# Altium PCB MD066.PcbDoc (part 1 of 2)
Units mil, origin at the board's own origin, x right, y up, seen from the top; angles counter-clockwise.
Board outline 4255 x 2850 mil, 4 copper layers (Top Layer, Ground, Power, Bottom Layer), stack 61.6 mil thick; 158 components, 78 nets, 405 pads, 639 vias.
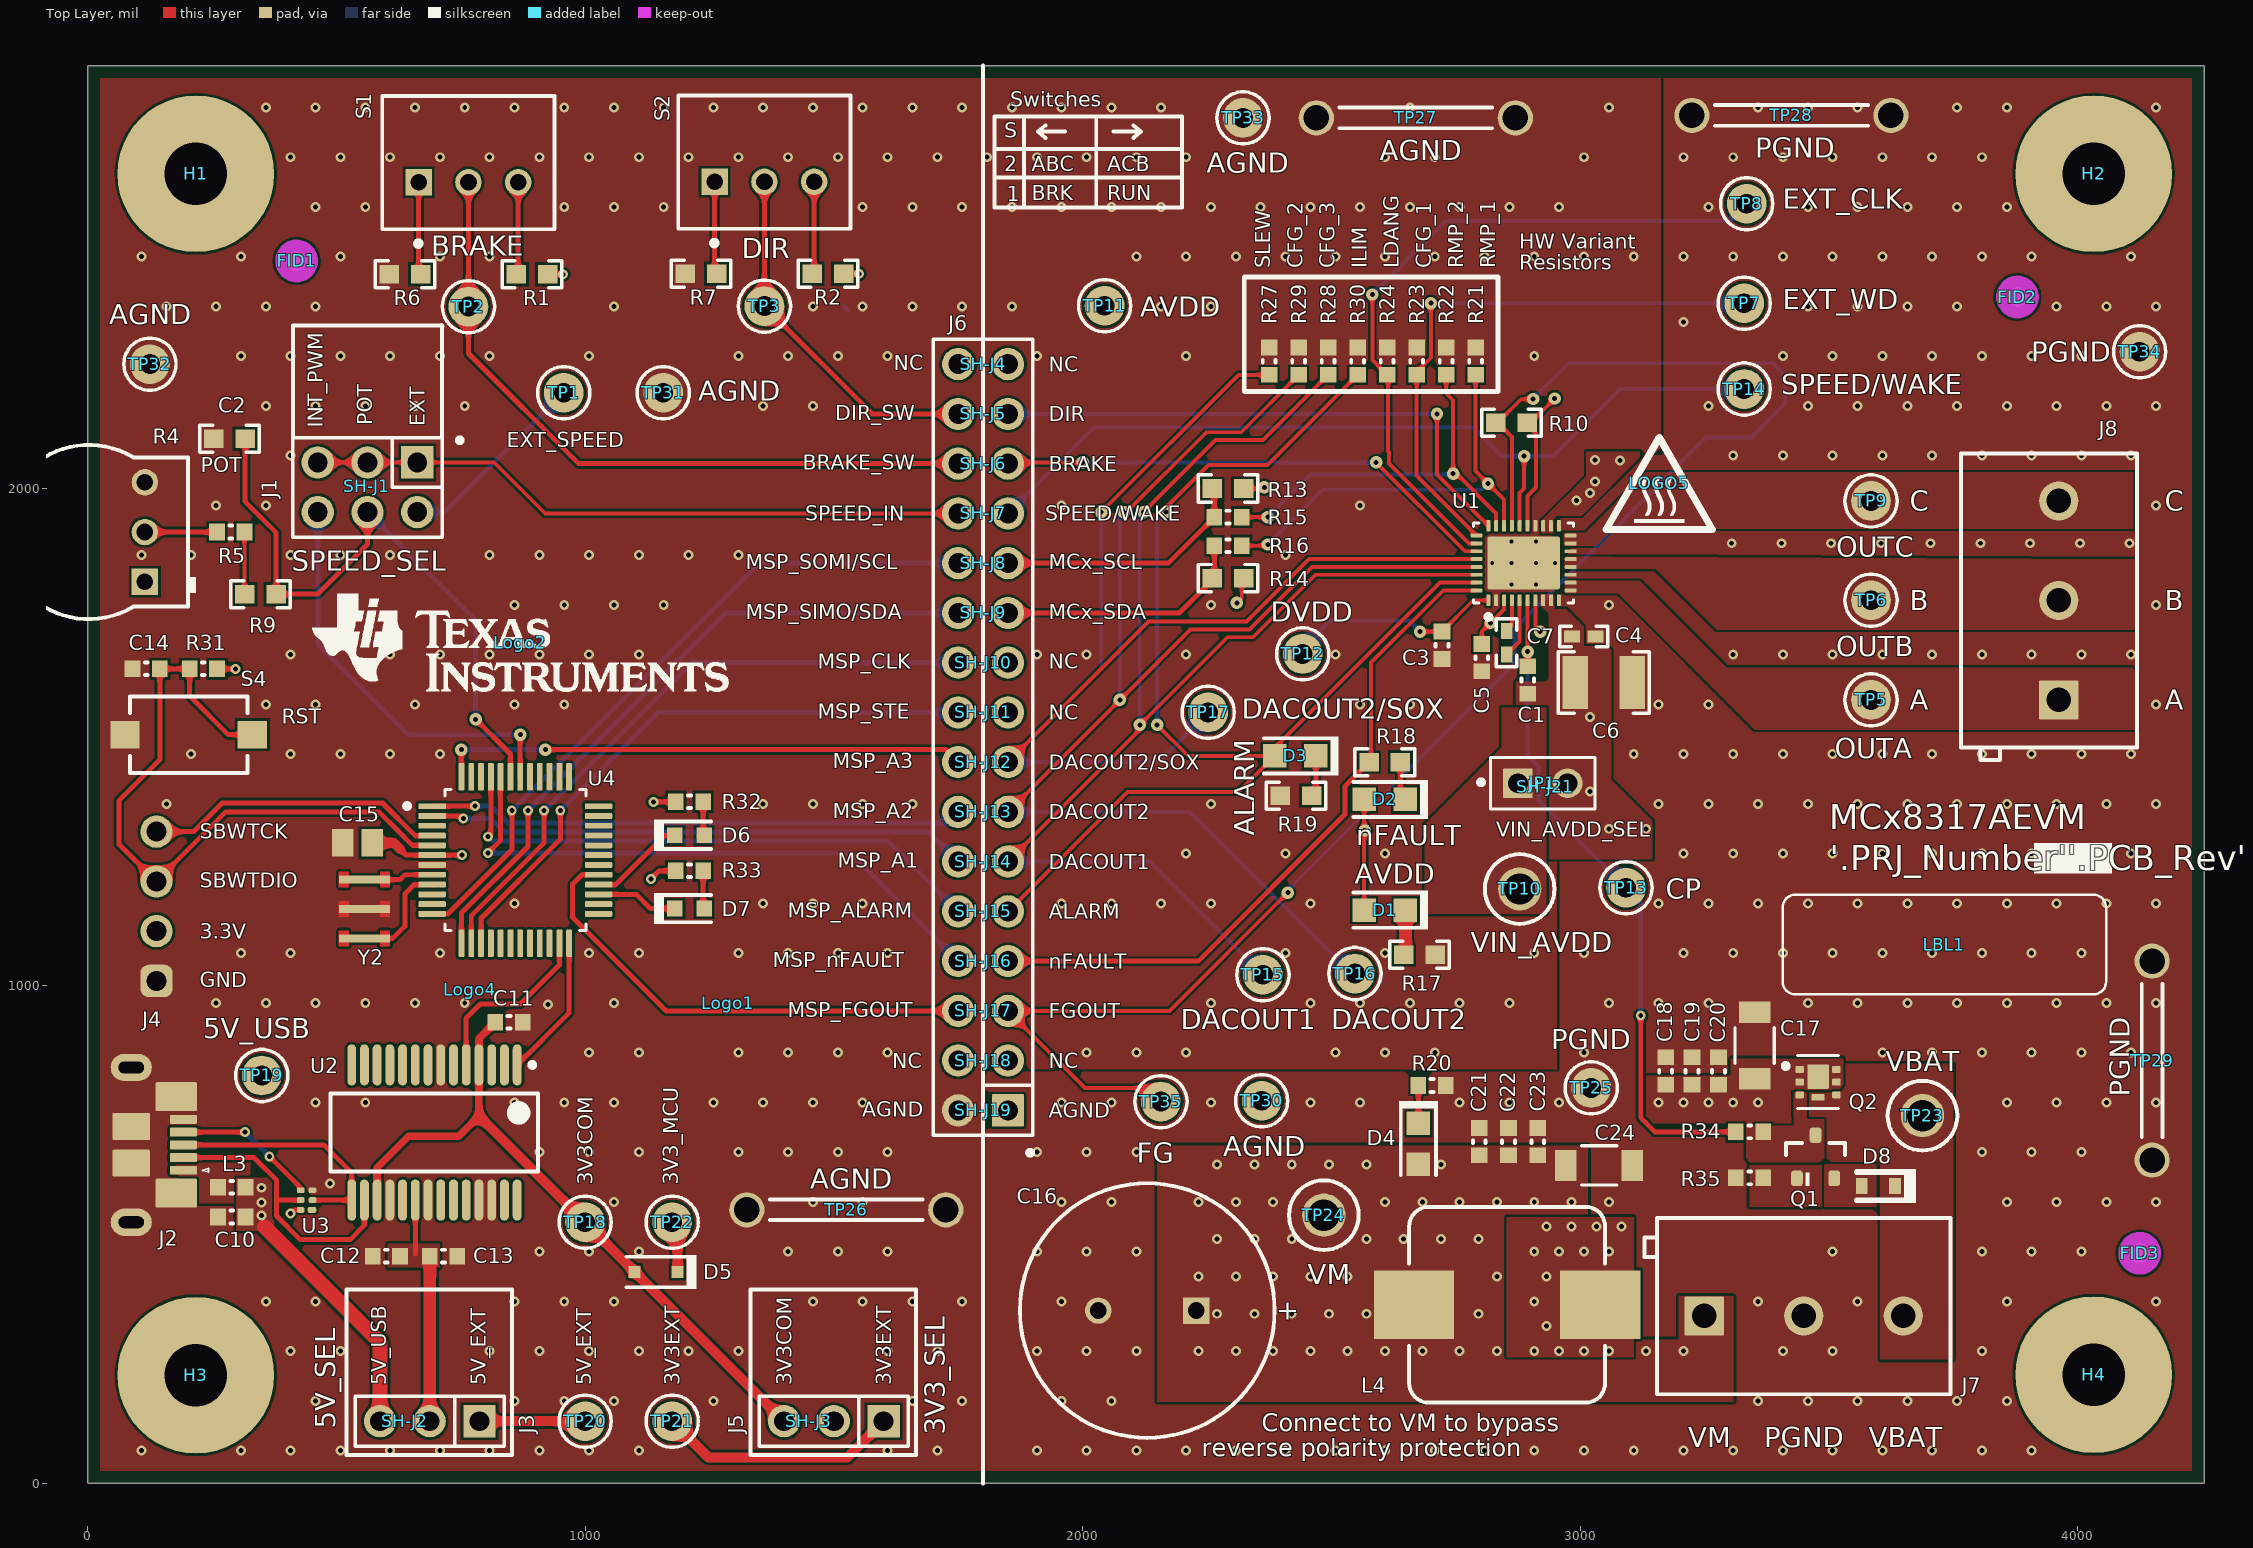
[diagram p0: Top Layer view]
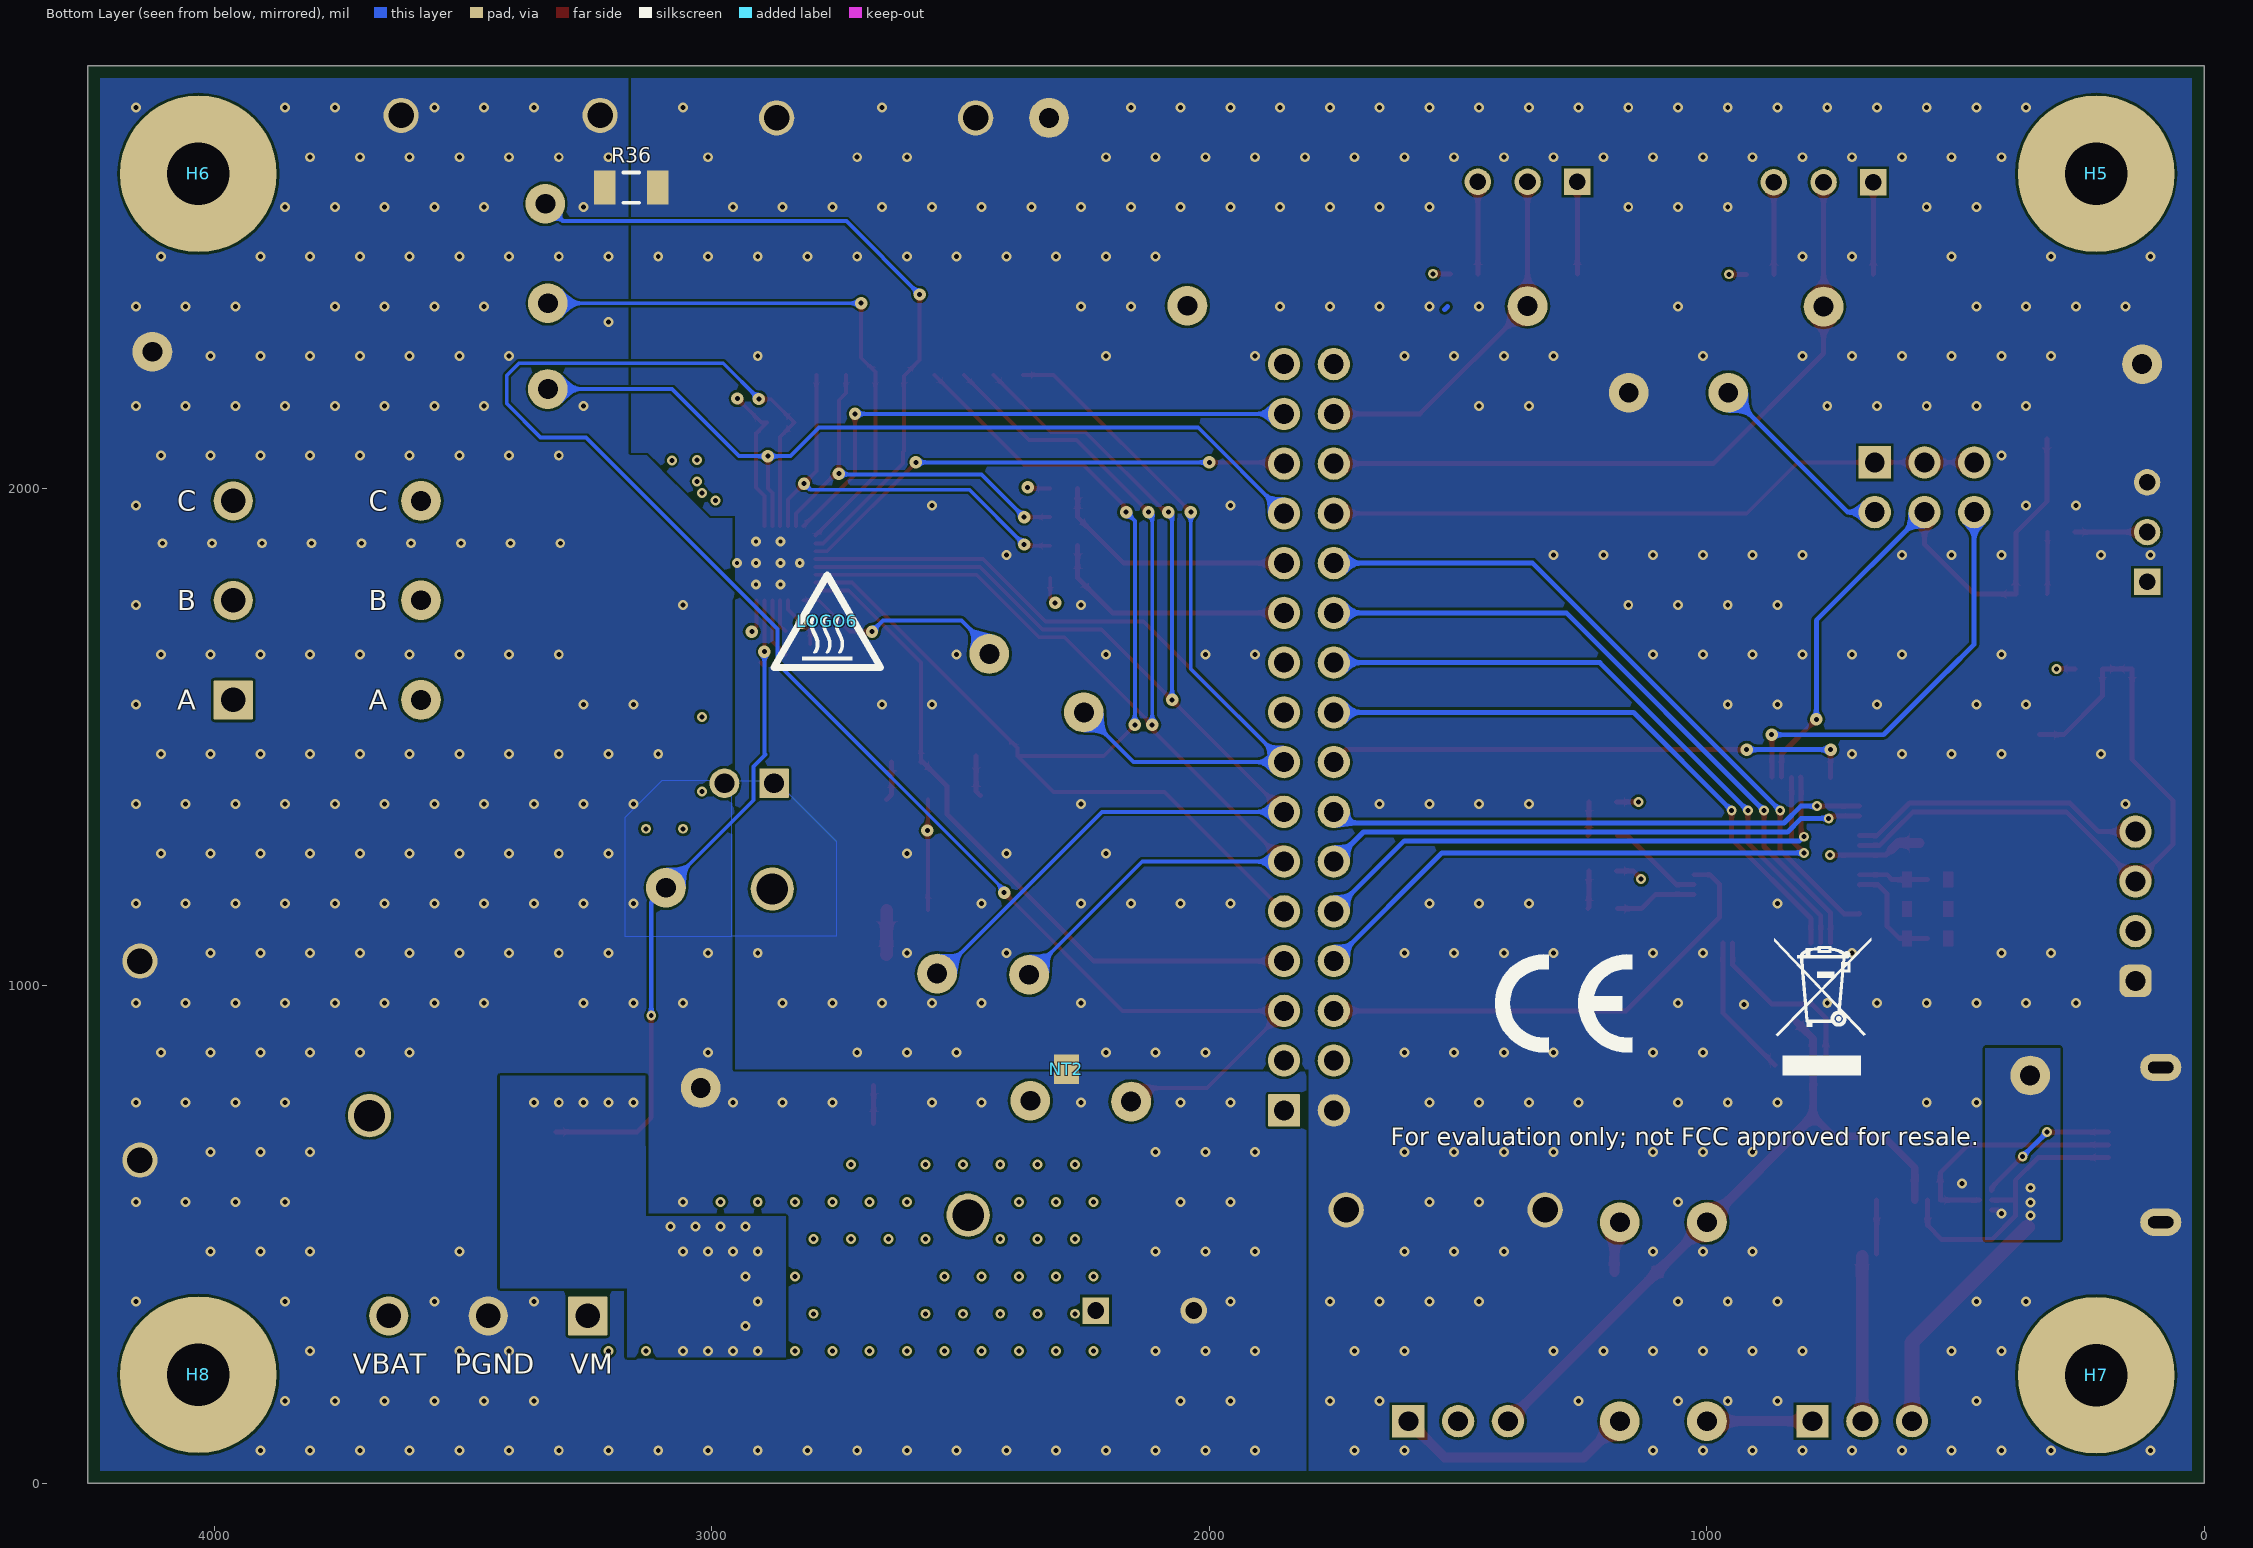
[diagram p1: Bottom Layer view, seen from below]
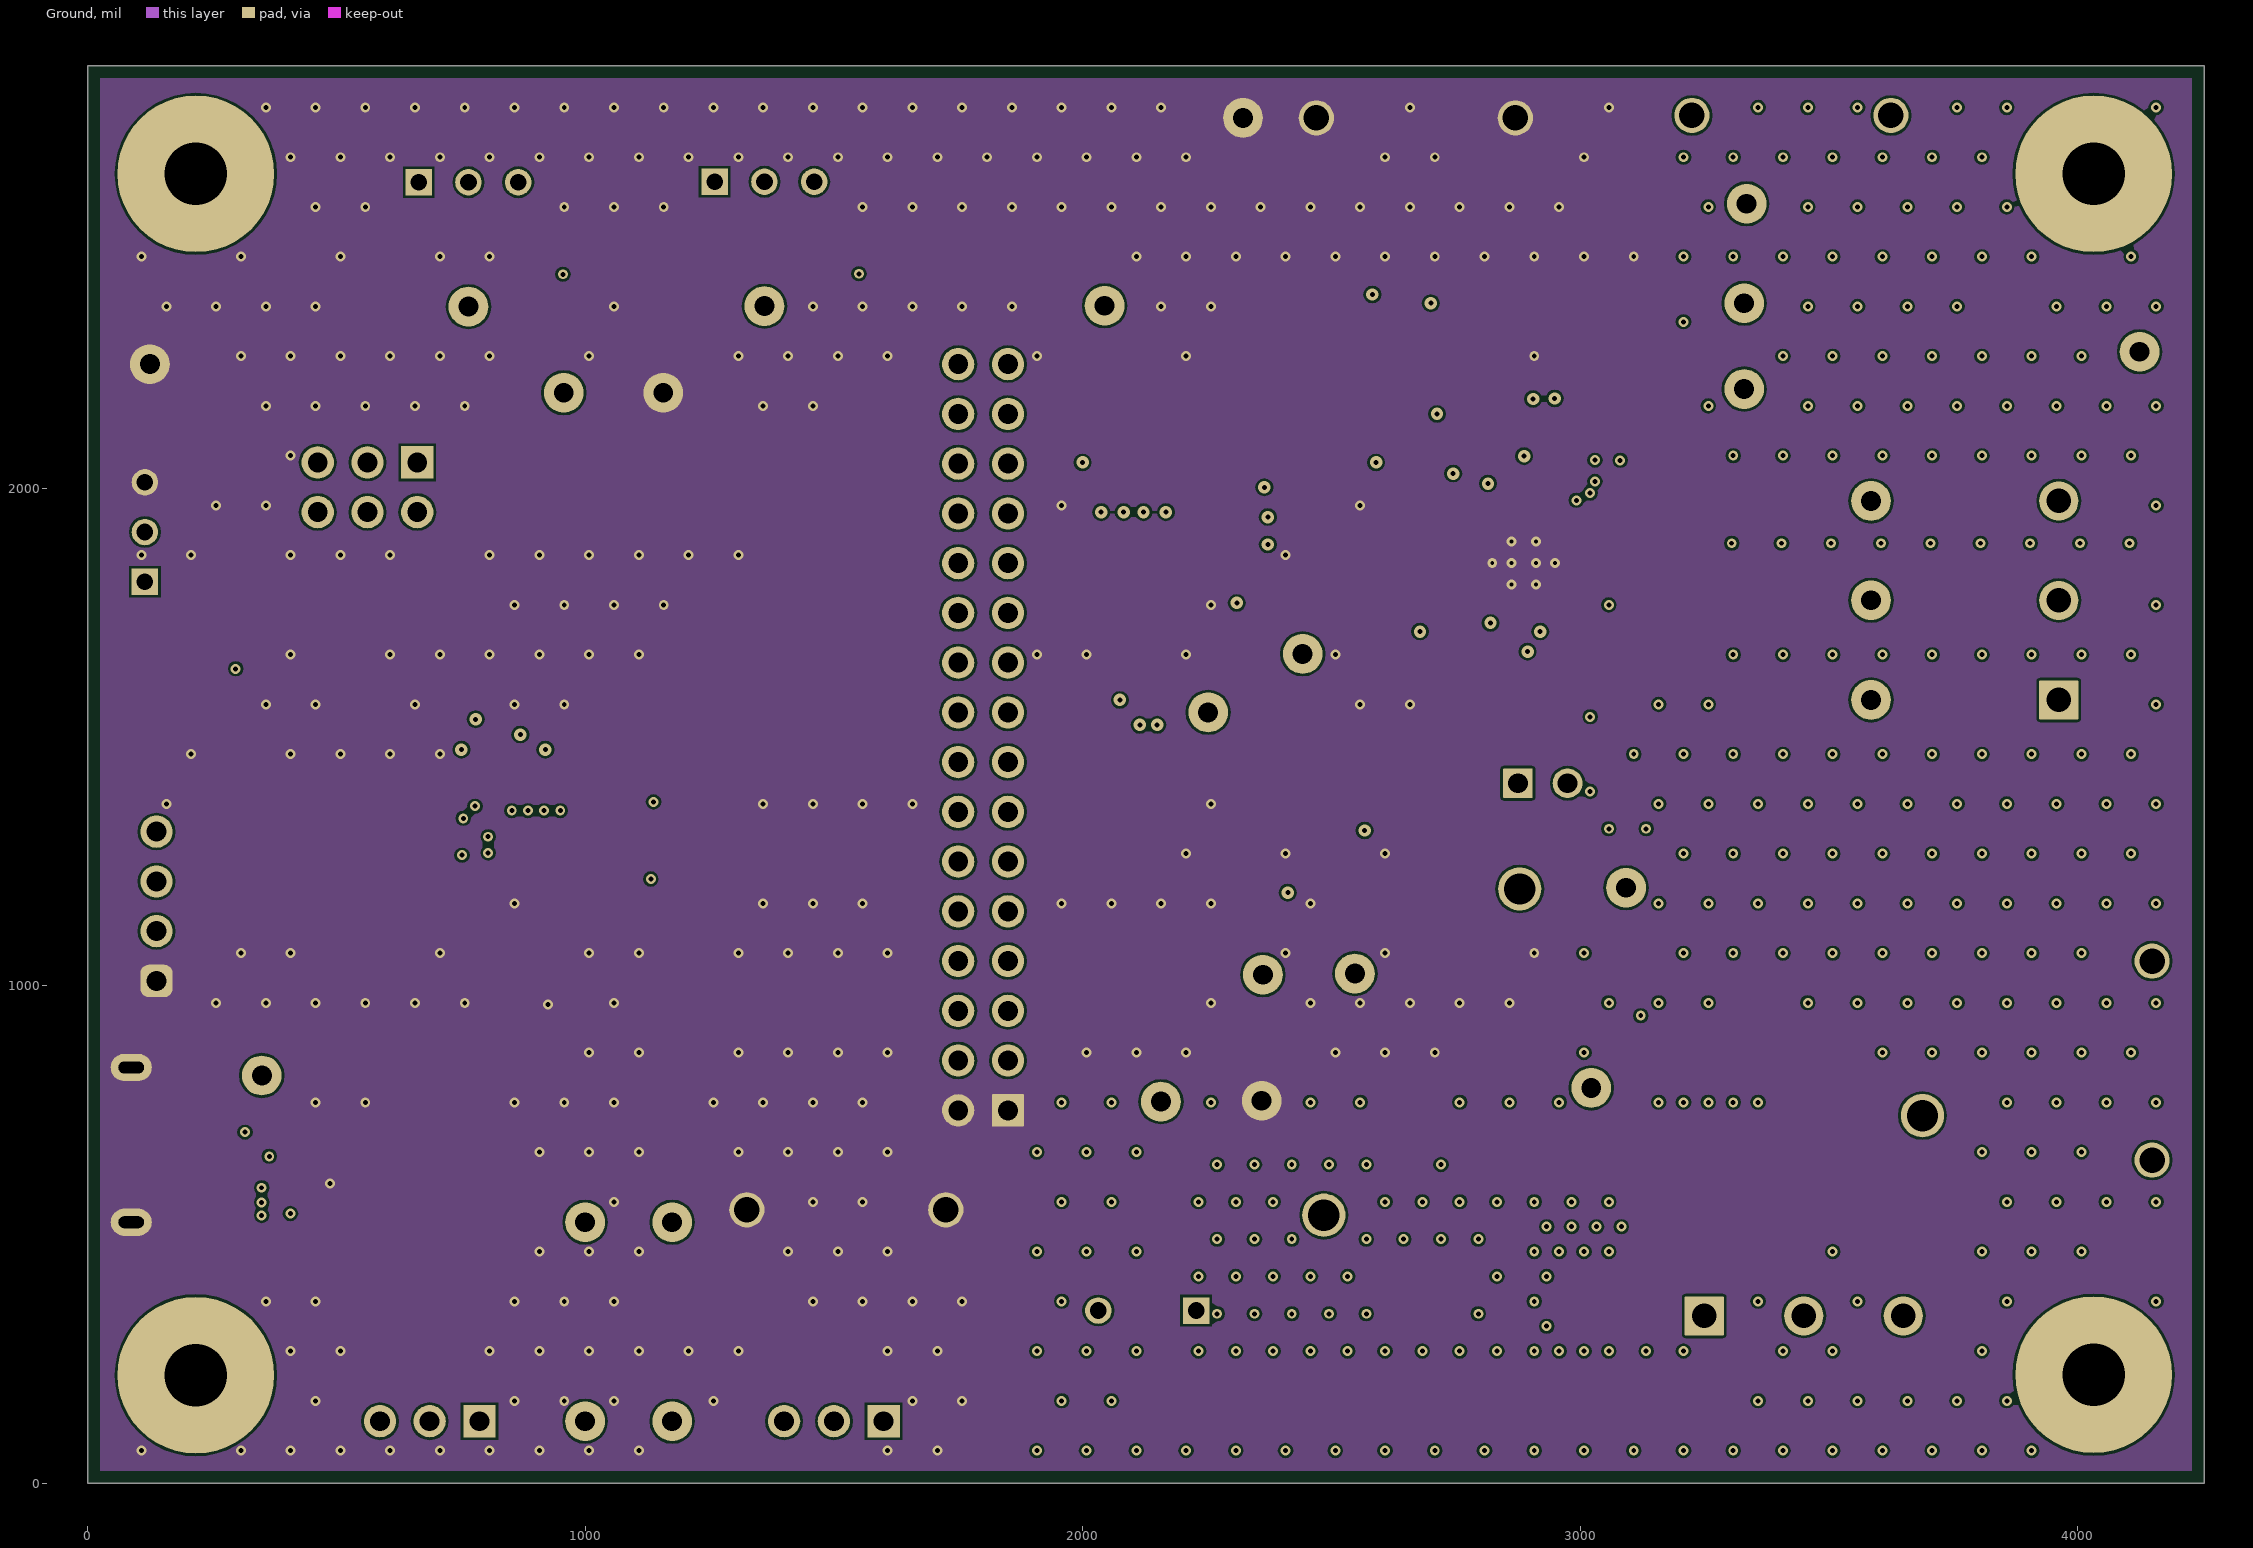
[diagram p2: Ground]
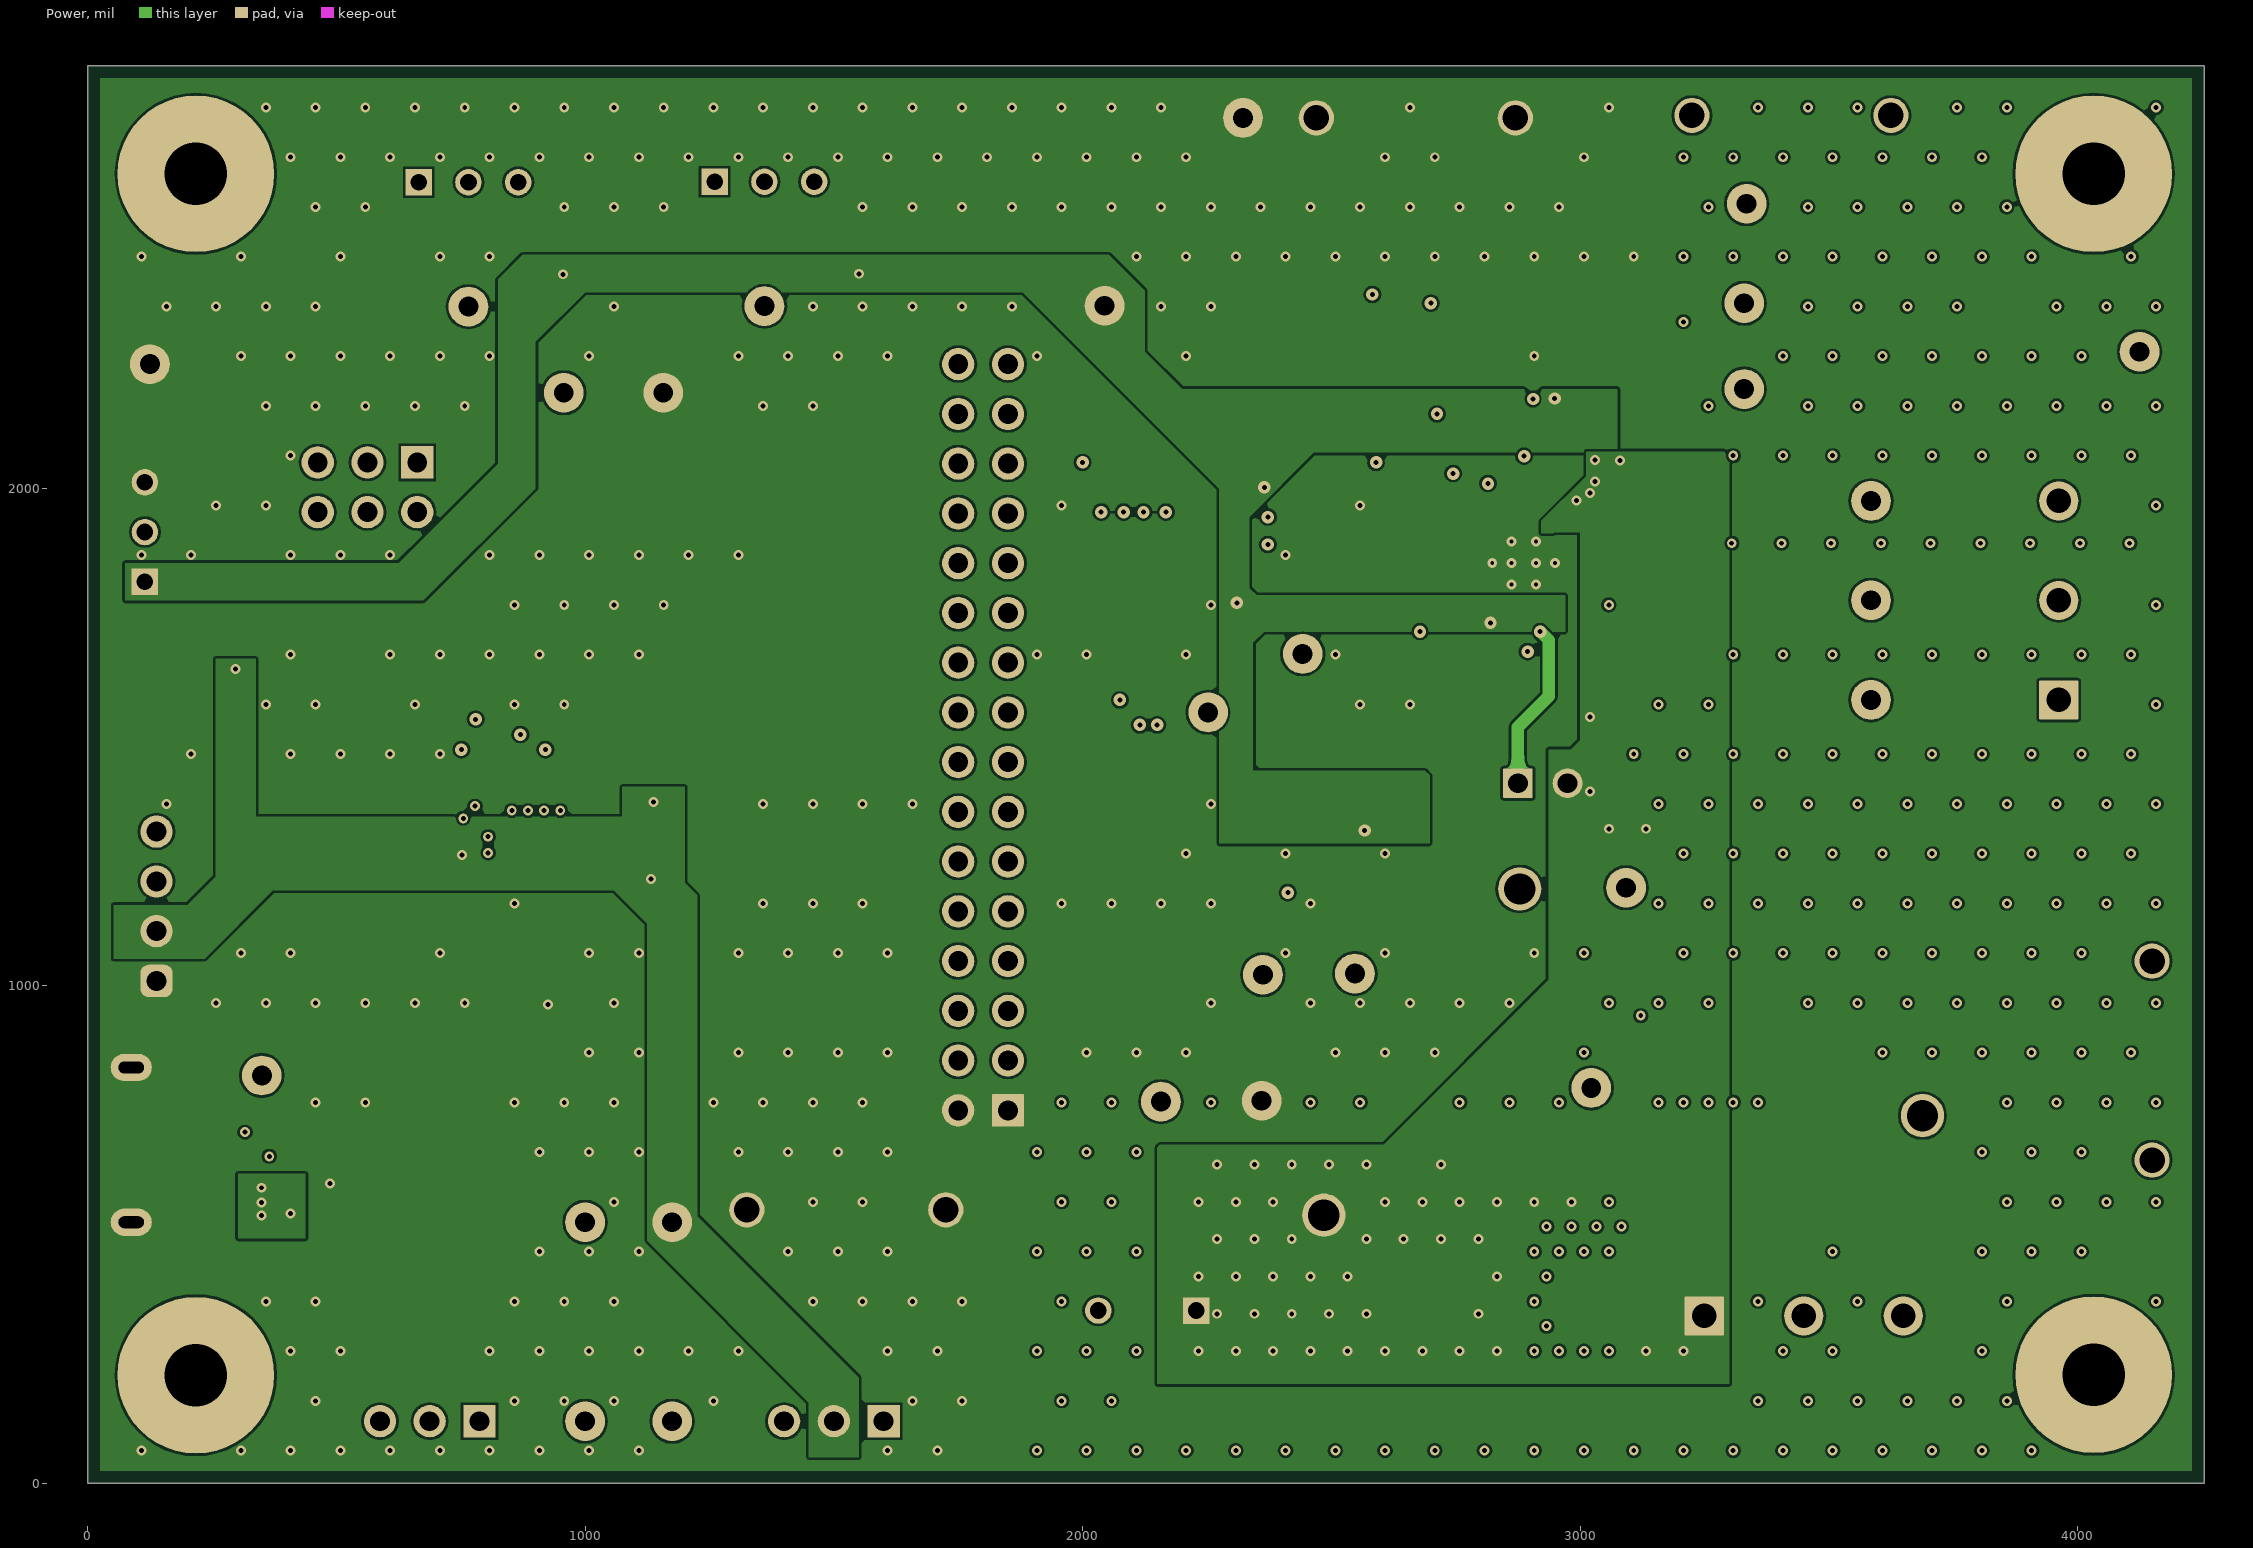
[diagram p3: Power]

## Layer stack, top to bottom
Top Solder: solder mask 0.4, Solder Resist, Dk 3.5
Top Layer: signal copper 1.4
Dielectric 1: prepreg 8, FR-4, Dk 4.2
Ground: signal copper 1.4
Dielectric 2: core 40, FR-4, Dk 4.2
Power: signal copper 1.4
Dielectric 3: prepreg 8, FR-4, Dk 4.2
Bottom Layer: signal copper 1.4
Bottom Solder: solder mask 0.4, Solder Resist, Dk 3.5

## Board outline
0,0 0,2850 4255,2850 4255,0

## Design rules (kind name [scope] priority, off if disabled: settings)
AcuteAngle [All] p1: minimum=4.50000000000000E+0001 checktracksonly=FALSE
AssemblyTestPointUsage [All] p1: valid=2
BoardOutlineClearance BoardOutlineClearance_MountingHoles [OnCopper and InComponentClass('Mounting Holes')] p1: gap=39.37 ignorepadtopadclearanceinfootprint=FALSE
BoardOutlineClearance BoardOutlineClearance_Poly [OnCopper and IsPoly] p2: gap=25 ignorepadtopadclearanceinfootprint=FALSE
BoardOutlineClearance [OnCopper and Not InComponentClass('Logo') and not InComponentClass('FiducialMark') and not InRegion(1000,500,4000,800) and not InPoly] p3: gap=30 ignorepadtopadclearanceinfootprint=FALSE
Clearance "Stitching AGND" [IsStitchingVia and InNet('AGND') vs (IsVia and (Not IsStitchingVia)) Or IsPad] p1: gap=70 ignorepadtopadclearanceinfootprint=TRUE
Clearance Clearance_Keepouts [((IsTrack Or IsArc) And Not InPoly) And IsFree and IsKeepOut vs ((IsTrack Or IsArc) And Not InPoly) And IsFree and IsKeepOut] p2: gap=0 ignorepadtopadclearanceinfootprint=FALSE
Clearance Clearance_Poly [InPolygon] p3: gap=7.87 ignorepadtopadclearanceinfootprint=TRUE except(5: Arc-Fill Arc-Poly Arc-Region Track-Fill Track-Poly Track-Region SMDPad-Fill SMDPad-Poly SMDPad-Region THPad-Fill THPad-Poly THPad-Region Via-Fill Via-Poly Via-Region Fill-Fill Fill-Poly Fill-Region Poly-Poly Poly-Region Region-Region)
Clearance Clearance_FiducialMark [IsKeepOut and InComponentClass('FiducialMark') vs IsPad and InComponentClass('FiducialMark')] p4: gap=0 ignorepadtopadclearanceinfootprint=FALSE
Clearance [All] p5: gap=7.87 ignorepadtopadclearanceinfootprint=TRUE
ComponentClearance ComponentClearance_MountingHoles_FiducialMarks [InComponentClass('Mounting Holes') vs InComponentClass('FiducialMark')] p1: gap=50 collisioncheckmode=3 verticalgap=10 showdistances=FALSE
ComponentClearance ComponentClearance_Shunt [InComponentClass('Header') vs InComponentClass('Shunt')] p2: gap=0 collisioncheckmode=3 verticalgap=0 showdistances=FALSE
ComponentClearance ComponentClearance_Logo [InComponentClass('Logo')] p3: gap=50 collisioncheckmode=3 verticalgap=10 showdistances=FALSE
ComponentClearance ComponentClearance_ScrewToNut [(HasFootprint('NY PMS 440 0025 PH')) vs (HasFootprint('Keystone_1902C'))] p4: gap=5 collisioncheckmode=3 verticalgap=10 showdistances=FALSE
ComponentClearance ComponentClearance_MountingHoles [InComponentClass('Mounting Holes')] p5: gap=150 collisioncheckmode=3 verticalgap=100000 showdistances=FALSE
ComponentClearance ComponentClearance_SmallPassives [HasFootprint('0201*') or HasFootprint('0402*') or HasFootprint('0508') or HasFootprint('0603*') or HasFootprint('0612') or HasFootprint('0805*') or HasFootprint('0815*') or HasFootprint('0830*') or HasFootprint('1206*') or HasFootprint('1210*') or HasFootprint('1808*') or HasFootprint('1812*') or HasFootprint('1825*') or HasFootprint('2010*') or HasFootprint('2220*') or HasFootprint('2225*') or HasFootprint('2512*') or HasFootprint('2728*') or HasFootprint('3518*') vs HasFootprint('0201*') or HasFootprint('0402*') or HasFootprint('0508') or HasFootprint('0603*') or HasFootprint('0612') or HasFootprint('0805*') or HasFootprint('0815*') or HasFootprint('0830*') or HasFootprint('1206*') or HasFootprint('1210*') or HasFootprint('1808*') or HasFootprint('1812*') or HasFootprint('1825*') or HasFootprint('2010*') or HasFootprint('2220*') or HasFootprint('2225*') or HasFootprint('2512*') or HasFootprint('2728*') or HasFootprint('3518*')] p6: gap=14.96 collisioncheckmode=3 verticalgap=10 showdistances=FALSE
ComponentClearance ComponentClearance_THtoSMT [IsThruComponent vs IsSMTComponent] p7: gap=0 collisioncheckmode=3 verticalgap=0 showdistances=FALSE
ComponentClearance ComponentClearance_THtoTH [IsThruComponent vs IsThruComponent] p8: gap=0 collisioncheckmode=3 verticalgap=0 showdistances=FALSE
ComponentClearance [All] p9: gap=0 collisioncheckmode=3 verticalgap=0 showdistances=FALSE
DiffPairsRouting [All] p1: maxlimit=100 minlimit=10 mostfreqgap=10 toplayer_minwidth=15 toplayer_maxwidth=15 toplayer_prefwidth=15 midlayer1_minwidth=15 midlayer1_maxwidth=15 midlayer1_prefwidth=15 midlayer2_minwidth=15 midlayer2_maxwidth=15 midlayer2_prefwidth=15 bottomlayer_minwidth=15 bottomlayer_maxwidth=15 bottomlayer_prefwidth=15 maxuncoupledlength=1000
FabricationTestPointUsage TestPointUsage [All] p1: valid=2 allowmultiple=FALSE
FabricationTestpoint Testpoint [All] p1: side=3 testpointundercomponent=TRUE minsize=40 maxsize=100 preferedsize=60 minholesize=0 maxholesize=40 preferedholesize=32 testpointgrid=1 allowsidetop=TRUE allowsidebottom=TRUE usegrid=TRUE gridtolerance=0.01
FanoutControl Fanout_LCC [IsLCC] p1: bgadir=Out bgaviamode=Centered fanoutstyle=Auto fanoutdirection=Alternating viagrid=1 // Fanout_LCC (Default Rule)
FanoutControl Fanout_BGA [IsBGA] p2: bgadir=Out bgaviamode=Centered fanoutstyle=Auto fanoutdirection=Alternating viagrid=1 // Fanout_BGA (Default Rule)
FanoutControl Fanout_Default [All] p4: bgadir=Out bgaviamode=Centered fanoutstyle=Auto fanoutdirection=Alternating viagrid=1 // Fanout_Default (Default Rule)
FanoutControl Fanout_Small [(CompPinCount < 5)] p5: bgadir=Out bgaviamode=Centered fanoutstyle=Auto fanoutdirection=OutThenIn viagrid=1 // Fanout_Small (Default Rule)
HoleSize [All] p1: absolutevalues=TRUE maxlimit=200 minlimit=1 maxpercent=80.000 minpercent=20.000
MinimumAnnularRing MinimumAnnularRing_ThermalPadVias [IsVia and InAnyComponent] p1: minimumring=1
MinimumAnnularRing [All] p2: minimumring=1
MinimumSolderMaskSliver MinimumSolderMaskSliver_Logo [InComponentClass('Logo') vs InComponentClass('Logo')] p1: minsoldermaskwidth=0.7
MinimumSolderMaskSliver [All] p2: minsoldermaskwidth=1
PlaneConnect [All] p1: planeconnectstyle=Relief reliefexpansion=10 reliefentries=4 reliefconductorwidth=10 reliefairgap=10
PolygonConnect [All] p1: connectstyle=Direct reliefconductorwidth=10 reliefentries=4 polygonreliefangle="90 Angle" airgapwidth=10
RoutingVias ThermalPadVias [IsVia and InAnyComponent] p1: holewidth=7.87 width=19.68 viastyle="Through Hole" minholewidth=7.87 minwidth=19.68 maxholewidth=12.99 maxwidth=23.62
RoutingVias [All] p2: holewidth=10 width=25 viastyle="Through Hole" minholewidth=7 minwidth=20 maxholewidth=15 maxwidth=30
SilkToBoardRegionClearance [Not ((IsComment or IsDesignator) And (Hide <> 'False')) and not InRegion(1000,500,4000,800)] p1:
SilkToSilkClearance SilkToSilkClearance_Pb-FreeLogo [(HasFootprint('Pb-Free_Overlay_Medium') OR HasFootprint('Pb-Free_Overlay_Small')) vs (HasFootprint('Pb-Free_Overlay_Medium') OR HasFootprint('Pb-Free_Overlay_Small'))] p1: silktosilkclearance=1
SilkToSilkClearance [All] p2: silktosilkclearance=1
SilkToSolderMaskClearance [IsPad] p1: minsilkscreentomaskgap=1 clearancetoexposedcopper=TRUE
SolderMaskExpansion [All] p1: expansion=1.97
UnRoutedNet [All] p1: checkbadconnections=TRUE
Width [All] p1: maxlimit=100 minlimit=6 preferedwidth=10 checkconnectedcopper=TRUE
14 further rules are at their usual default settings.

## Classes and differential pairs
component class Label: LBL1
component class "Mounting Holes": H1 H2 H3 H4
component class MD066_INTERFACE: C10 C11 C12 C13 C14 C15 D5 D6 D7 J2 J3 J4 J5 J6 L3 R31 R32 R33 S4 SH-J2 SH-J3 SH-J4 SH-J5 SH-J6 SH-J7 SH-J8 SH-J9 SH-J10 SH-J11 SH-J12 SH-J13 SH-J14 SH-J15 SH-J16 SH-J17 SH-J18 SH-J19 TP18 TP19 TP20 TP21 TP22 U2 U3 U4 Y2
component class MD066_CONTROL: C2 J1 R1 R2 R4 R5 R6 R7 R9 S1 S2 SH-J1 TP1 TP2 TP3
component class Shunt: SH-J1 SH-J2 SH-J3 SH-J4 SH-J5 SH-J6 SH-J7 SH-J8 SH-J9 SH-J10 SH-J11 SH-J12 SH-J13 SH-J14 SH-J15 SH-J16 SH-J17 SH-J18 SH-J19 SH-J21
component class MD066_POWER_AND_CONNECTORS: AGND AGND1 C16 C17 C18 C19 C20 C21 C22 C23 C24 D8 J7 J8 J10 J11 JP1 L4 NT2 PGND PGND2 PGND3 Q1 Q2 R34 R35 R36 R45 SH-J21 TP10 TP23 TP24 TP25 TP26 TP27 TP28 TP29 TP30 TP31 TP32 TP33 TP34 TP_AGND1 TP_AGND2 TP_PGND vm VM1
component class MD066_DRIVER: 1 A1 B1 C1 C3 C4 C5 C6 C7 D1 D2 D3 D4 D? ILIM1 R10 R13 R14 R15 R16 R17 R18 R19 R20 R21 R22 R23 R24 R27 R28 R29 R30 TP5 TP6 TP7 TP8 TP9 TP11 TP12 TP13 TP14 TP15 TP16 TP17 TP35 U1
component class Header: J1 J3 J4 J5 J6 J10
component class Logo: Logo2
component class MD066_HARDWARE: FID1 FID2 FID3 H1 H2 H3 H4 H5 H6 H7 H8 LBL1 Logo1 Logo2 Logo3 Logo4 LOGO5 LOGO6 ZZ1 ZZ2 ZZ3 ZZ4
component class FiducialMark: FID1 FID2 FID3
component class AssemblyNote: ZZ1 ZZ2 ZZ3 ZZ4

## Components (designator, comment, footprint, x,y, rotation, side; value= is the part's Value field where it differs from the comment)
C1 "EMK107B7105KAHT" 0603L 2894.94,1615 r270 top value=1uF
C2 "0603ZC101KAT2A" 0603 285,2100 r180 top value=100pF
C3 "C0603C105K9RACAUTO" 0603L 2722.5,1685 r90 top value=1uF
C4 "C1005X6S1H104K050BB" 0402 3007.5,1702.5 r0 top value=0.1uF
C5 "C0603C105K9RACAUTO" 0603L 2802.5,1660 r90 top value=1uF
C6 "GRM32ER71J106KA12L" 1210_270 3047.5,1610 r0 top value=10uF
C7 "C1005X6S1H104K050BB" 0402 2852.5,1690 r90 top value=0.1uF
C10 "0603ZC104KAT2A" 0603L 289.64,535.59 r180 top value=0.1uF
C11 "0603ZC104KAT2A" 0603L 847.14,927.09 r0 top value=0.1uF
C12 "GRM188Z71A475ME15D" 0603L 600.29,456.84 r0 top value=4.7uF
C13 "0603ZC104KAT2A" 0603L 715.29,456.96 r0 top value=0.1uF
C14 "885012206034" 0603L 117.5,1637.5 r180 top value=1000pF
C15 "885012207103" 0805L 542.5,1287.5 r180 top value=1uF
C16 "ELXZ630ELL331MK20S" Chemi-Con_1250x2000 2130,347.5 r180 top value=330uF
C17 "CL31B105KCHNNNE" 1206_180 3350.96,880.34 r90 top value=1uF
C18 "CGA3E3X7S2A104K080AB" 0603L 3172.01,828.83 r90 top value=0.1uF
C19 "CGA3E2X7R2A103K080AA" 0603L 3225.22,828.83 r90 top value=0.01uF
C20 "CGA3E2X7R2A102K080AA" 0603L 3278.42,828.83 r90 top value=1000pF
C21 "CGA3E2X7R2A102K080AA" 0603L 2797.51,686.94 r90 top value=1000pF
C22 "CGA3E2X7R2A103K080AA" 0603L 2856.26,686.94 r90 top value=0.01uF
C23 "CGA3E3X7S2A104K080AB" 0603L 2915.01,686.94 r90 top value=0.1uF
C24 "CL31B105KCHNNNE" 1206_180 3038.46,639.14 r0 top value=1uF
D1 "AVDD" LTST-C170KGKT_Green 2607.5,1152.5 r0 top value=Green
D2 "nFAULT" LED_LTST-C170_Red 2607.5,1375 r0 top value=Red
D3 "ALARM" LED_LTST-C170_Red 2427.5,1462.5 r0 top value=Red
D4 "LTST-C170KGKT" LTST-C170KGKT_Green 2675,682.5 r90 top value=Green
D5 "BAT165E6327HTSA1" SOD-323 1142.5,425 r180 top value=40V
D6 "LTST-C190KRKT" LED_LTST-C190_Red 1209.64,1302.7 r180 top value=Red
D7 "LTST-C190GKT" LED_LTST-C190 1209.64,1155.59 r180 top value=Green
D8 "CDSU101A" SOD-523F 3599.64,597.8 r180 top value=90V
FID1 "Fiducial" Fiducial10-20 420,2457.5 r0 top
FID2 "Fiducial" Fiducial10-20 3879.4,2385 r0 top
FID3 "Fiducial" Fiducial10-20 4125,462.5 r0 top
H1 "NY PMS 440 0025 PH" "NY PMS 440 0025 PH" 217.5,2632.5 r0 top
H2 "NY PMS 440 0025 PH" "NY PMS 440 0025 PH" 4032.5,2632.5 r0 top
H3 "NY PMS 440 0025 PH" "NY PMS 440 0025 PH" 217.5,217.5 r0 top
H4 "NY PMS 440 0025 PH" "NY PMS 440 0025 PH" 4032.5,218.36 r0 top
H5 "Nut" Keystone_1902C 217.5,2632.5 r180 bottom
H6 "Nut" Keystone_1902C 4032.5,2632.5 r180 bottom
H7 "Nut" Keystone_1902C 217.5,217.5 r180 bottom
H8 "Nut" Keystone_1902C 4032.5,218.36 r180 bottom
J1 "SPEED_CTRL_SEL" TSW-103-07-G-D 562.5,2002.5 r180 top
J2 "1051640001" Molex_1051640001 30.41,680.59 r270 top
J3 "Header_3x1" PBC03SAAN 687.5,125 r180 top
J4 "TSW-104-07-G-S" TSW-104-07-G-S 138.36,1160.18 r90 top
J5 "Header_3x1" PBC03SAAN 1500,125 r180 top
J6 "TSW-116-07-G-D" TSW-116-07-G-D 1800,1500 r90 top
J7 "MOTOR_OUT" On-Shore_ED120_3DS 3449.83,336.64 r0 top
J8 "MOTOR_OUT" On-Shore_ED120_3DS 3962.5,1775 r90 top
JP1 "VIN_AVDD_SEL" FP-MTLW-102-07-G-S-230_HDR2-MFG 2925,1407.5 r0 top
L3 "BLM18SG121TZ1D" 0603L 289.64,595.24 r180 top
L4 "SRP1038A-1R0M" SRP1038A 2853.46,359.14 r180 top value=1uH
LBL1 "THT-14-423-10" Label_650x200 3732.5,1083.2 r180 top
Logo1 "CE Mark" CE_Mark_5mm 1287.85,965 r180 top
Logo2 "Texas Instruments" TI_Stacked_Overlay_Small 870,1690 r0 top
Logo3 "FCC disclaimer" FCC_disclaimer 8817.5,5262.5 r90 top
Logo4 "WEEE logo" WEEE_Minimum 769.14,992.5 r180 top
LOGO5 "CAUTION HOT SURFACE" IEC_HotSurface_Small 3159.37,2010.26 r0 top
LOGO6 "CAUTION HOT SURFACE" IEC_HotSurface_Small 2768.31,1733.62 r180 bottom
NT2 "Net-Tie" Net-Tie_50milWide_30milLong 2287.5,832.5 r270 bottom net-tie
Q1 "FMMT620TA" SOT-23L 3473.46,656.64 r90 top value="80 V"
Q2 "BUK9D23-40EX" FP-BUK9D23-40EX_SOT1220-MFG 3478.46,806.64 r0 top
R1 "RNCF0603TKY10K0" 0603 893,2430.7 r0 top value=10.0k
R2 "RNCF0603TKY10K0" 0603 1488,2431.7 r0 top value=10.0k
R4 "3352T-1-253LF" Bourns_3352T 115,1912.5 r90 top value="25 kohm"
R5 "ERJ-3GEY0R00V" 0603L 287.5,1912.5 r180 top value=0
R6 "RNCF0603TKY10K0" 0603 637.94,2430.7 r0 top value=10.0k
R7 "RNCF0603TKY10K0" 0603 1232.88,2431.7 r0 top value=10.0k
R9 "RT0603BRD0747RL" 0603 347.5,1787.5 r180 top value=47.0
R10 "RCG060310K0FKEA" 0603 2862.03,2132.5 r0 top value=10.0k
R13 "RT0603DRE071K74L" 0603 2292.5,2000 r0 top value=1.74k
R14 "RT0603DRE071K74L" 0603 2292.5,1820 r0 top value=1.74k
R15 "ERJ-3GEY0R00V" 0603L 2292.5,1942.5 r0 top value=0
R16 "ERJ-3GEY0R00V" 0603L 2292.5,1885 r0 top value=0
R17 "RC0603FR-071KL" 0603 2677.5,1062.5 r180 top value=1.00k
R18 "RC0603FR-071KL" 0603 2607.5,1450 r0 top value=1.00k
R19 "ERJ-3GEYJ222V" 0603 2428.98,1382.5 r0 top value=2.2k
R20 "RT0603BRD074K7L" 0603L 2702.56,800 r180 top value=4.70k
R21 "ERJ-3GEY0R00V" 0603L 2790.1,2256 r90 top value=0
R22 "ERJ-3GEY0R00V" 0603L 2730.8,2256 r90 top value=0
R23 "ERJ-3GEY0R00V" 0603L 2671.5,2256 r90 top value=0
R24 "ERJ-3GEY0R00V" 0603L 2612.2,2256 r90 top value=0
R27 "ERJ-3GEY0R00V" 0603L 2375,2256 r90 top value=0
R28 "ERJ-3GEY0R00V" 0603L 2493.6,2256 r90 top value=0
R29 "ERJ-3GEY0R00V" 0603L 2434.3,2256 r90 top value=0
R30 "ERJ-3GEY0R00V" 0603L 2552.9,2256 r90 top value=0
R31 "RC0603JR-0747KL" 0603L 232.5,1637.5 r0 top value=47k
R32 "RC0603JR-07470RL" 0603L 1209.64,1370.2 r180 top value=470
R33 "RC0603JR-07470RL" 0603L 1209.64,1231.43 r180 top value=470
R34 "CRCW060310K0JNEA" 0603L 3340.96,706.64 r0 top value=10k
R35 "CRCW060310K0JNEA" 0603L 3340.96,614.14 r180 top value=10k
R36 "RCA12060000ZSEA" 1206L 3162.5,2605 r0 bottom value=0
S1 "SW_SPDT_COM2_1_3" SW_B12AP 765.44,2655.07 r90 top
S2 "SW_SPDT_COM2_1_3" SW_B12AP 1360.44,2656.07 r90 top
S4 "SW_SPST-single" SW_434121025816 203,1505.27 r180 top
SH-J1 "SNT-100-BK-G" SNT-100-BK-G 561.05,2005 r90 top value=1x2
SH-J2 "SNT-100-BK-G" SNT-100-BK-G 637.5,125 r0 top value=1x2
SH-J3 "SNT-100-BK-G" SNT-100-BK-G 1450,125 r0 top value=1x2
SH-J4 "SNT-100-BK-G" SNT-100-BK-G 1800,2250 r180 top value=1x2
SH-J5 "SNT-100-BK-G" SNT-100-BK-G 1800,2150 r180 top value=1x2
SH-J6 "SNT-100-BK-G" SNT-100-BK-G 1800,2050 r180 top value=1x2
SH-J7 "SNT-100-BK-G" SNT-100-BK-G 1800,1950 r180 top value=1x2
SH-J8 "SNT-100-BK-G" SNT-100-BK-G 1800,1850 r180 top value=1x2
SH-J9 "SNT-100-BK-G" SNT-100-BK-G 1800,1750 r180 top value=1x2
SH-J10 "SNT-100-BK-G" SNT-100-BK-G 1800,1650 r180 top value=1x2
SH-J11 "SNT-100-BK-G" SNT-100-BK-G 1800,1550 r180 top value=1x2
SH-J12 "SNT-100-BK-G" SNT-100-BK-G 1800,1450 r180 top value=1x2
SH-J13 "SNT-100-BK-G" SNT-100-BK-G 1800,1350 r180 top value=1x2
SH-J14 "SNT-100-BK-G" SNT-100-BK-G 1800,1250 r180 top value=1x2
SH-J15 "SNT-100-BK-G" SNT-100-BK-G 1800,1150 r180 top value=1x2
SH-J16 "SNT-100-BK-G" SNT-100-BK-G 1800,1050 r180 top value=1x2
SH-J17 "SNT-100-BK-G" SNT-100-BK-G 1800,950 r0 top value=1x2
SH-J18 "SNT-100-BK-G" SNT-100-BK-G 1800,850 r0 top value=1x2
SH-J19 "SNT-100-BK-G" SNT-100-BK-G 1800,750 r0 top value=1x2
SH-J21 "SNT-100-BK-G" SNT-100-BK-G 2930.07,1400 r180 top value=1x2
TP1 "EXT_SPEED" Keystone5002 956.95,2192.5 r90 top
TP2 "BRAKE_SW" Keystone5002 765.44,2365.7 r270 top
TP3 "DIR_SW" Keystone5002 1360.44,2366.7 r270 top
TP5 "OUTA" Keystone5000 3585,1575 r90 top
TP6 "OUTB" Keystone5000 3585,1775.39 r90 top
TP7 "EXT_WD" Keystone5002 3330,2372.5 r90 top
TP8 "EXT_CLK" Keystone5002 3335,2572.5 r90 top
TP9 "OUTC" Keystone5000 3585,1975 r90 top
TP10 "VIN_AVDD" Keystone5005 2878.76,1195 r0 top
TP11 "AVDD" Keystone5000 2044.33,2367.5 r90 top
TP12 "DVDD" Keystone5000 2442.5,1667.5 r90 top
TP13 "CP" Keystone5000 3092.5,1197.5 r90 top
TP14 "SPEED/WAKE" Keystone5002 3330,2200 r90 top
TP15 "DACOUT1" Keystone5002 2362.5,1022.5 r90 top
TP16 "DACOUT2" Keystone5002 2547.5,1025 r90 top
TP17 "DACOUT2/SOX" Keystone5002 2252.5,1550 r90 top
TP18 "3V3COM" Keystone5000 1000,525 r90 top
TP19 "5V_USB" Keystone5000 350,820 r90 top
TP20 "5V_EXT" Keystone5000 1000,125 r90 top
TP21 "3V3EXT" Keystone5000 1175,125 r90 top
TP22 "3V3_MCU" Keystone5000 1175,525 r90 top
TP23 "VBAT" Keystone5005 3688.46,739.3 r180 top
TP24 "VM" Keystone5005 2485,539.22 r180 top
TP25 "PGND" Keystone5001 3022.5,795 r270 top
TP26 "AGND" Harwin_D3082-05 1525,550 r180 top
TP27 "AGND" Harwin_D3082-05 2670,2745 r180 top
TP28 "PGND" Harwin_D3082-05 3425,2750 r180 top
TP29 "PGND" Harwin_D3082-05 4150,850 r90 top
TP30 "AGND" Keystone5001 2360,769.18 r90 top
TP31 "AGND" Keystone5001 1156.95,2192.5 r90 top
TP32 "AGND" Keystone5001 125,2250 r90 top
TP33 "AGND" Keystone5001 2322.5,2745 r90 top
TP34 "PGND" Keystone5001 4125,2275 r90 top
TP35 "FG" Keystone5002 2157.5,767.5 r90 top
U1 "MCT8317A0IREER" REE0036A-MFG 2886.63,1850.2 r90 top
U2 "FT232RL" SSOP28_N 696.98,705.42 r270 top
U3 "TPD4E004DRYR" DRY0006A 440,569.59 r180 top
U4 "MSP430FR2355TPTR" PT0048A-MFG 859.64,1253.09 r0 top
Y2 "CSTCR4M00G55B-R0" Murata_CSTCR_G 556.22,1154.67 r270 top
ZZ1 "This Assembly Note is for PCB labels only" AssemblyNoteLabel 80,3460.5 r0 top
ZZ2 "These assemblies are ESD sensitive, ESD precautions shall be observed." AssemblyNote 80,3351.61 r0 top
ZZ3 "These assemblies must be clean and free from flux and all contaminants. Use of no clean flux is not acceptable." AssemblyNote 80,3263.06 r0 top
ZZ4 "These assemblies must comply with workmanship standards IPC-A-610 Class 2, unless otherwise specified." AssemblyNote 80,3174.5 r0 top

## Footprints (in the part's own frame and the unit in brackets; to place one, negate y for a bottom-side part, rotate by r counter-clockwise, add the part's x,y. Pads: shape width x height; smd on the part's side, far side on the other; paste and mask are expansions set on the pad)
0402 [mm] "0402 from SM-752 data"
  rect 0.8x0.6 smd: 1(-0.6,0) 2(0.6,0)
  silkscreen extent -1.22,-0.52 1.22,0.52, body extent -0.55,-0.3 0.55,0.3, height 0.6
0603 [mm] "0603 from SM-752 data"
  rect 1x0.95 smd: 1(-0.8,0) 2(0.8,0)
  silkscreen extent -1.52,-0.69 1.52,0.69, body extent -0.87,-0.47 0.87,0.47, height 1
0603L [mm] "0603 from SM-752 data"
  rect 0.8x0.85 smd: 1(-0.7,0) 2(0.7,0)
  silkscreen extent -0.07,-0.33 0.07,0.33, body extent -0.87,-0.47 0.87,0.47, height 1
0805L [mm] "0805 from SM-752 data"
  rect 1.1x1.4 smd: 1(-0.75,0) 2(0.75,0)
  body extent -1.1,-0.72 1.1,0.72, height 1.45
1206_180 [mm] "1206_180"
  rect 1.1x1.6 smd: 1(-1.7,0) 2(1.7,0)
  silkscreen extent -0.9,-1 0.9,1, body extent -1.75,-0.95 1.75,0.95, height 1.8
1206L [mm] "1206 from SM-752 data"
  rect 1.1x1.75 smd: 1(-1.35,0) 2(1.35,0)
  silkscreen extent -0.4,-0.77 0.4,0.77, body extent -1.7,-0.9 1.7,0.9, height 1.35
1210_270 [mm] "1210"
  rect 1.3x2.7 smd: 1(-1.45,0) 2(1.45,0)
  silkscreen extent -2.32,-1.57 2.32,1.57, body extent -1.7,-1.35 1.7,1.35, height 2.7
AssemblyNote [mil] "Assembly Note"
AssemblyNoteLabel [mil] "Assembly Note for PCB Labels"
Bourns_3352T [mm] "TH, 3-Leads, Body 9.53x8.89mm, Pitch 2.54mm"
  rect 1.35x1.35 hole 0.85: 1(-2.54,0)
  round 1.35 hole 0.85: 2(0,0) 3(2.54,0)
  silkscreen extent -4.44,-2.6 4.44,7.31, body extent -4.44,-2.21 4.45,7.32, height 3.81
CE_Mark_5mm [mil] "Minimum text height for CE Mark"
Chemi-Con_1250x2000 [mm] "TH, 2-Leads, Dia 12.5mm, Lead Sapcing 5mm"
  rect 1.35x1.35 hole 0.85: 1(-2.5,0)
  round 1.35 hole 0.85: 2(2.5,0)
  silkscreen extent -6.5,-6.5 6.5,6.5, body extent -6.5,-6.5 6.51,6.5, height 21.5
DRY0006A [mm] "USON-6"
  rrect67% 0.45x0.3 smd paste-0.05 mask-0.05: 1(-0.275,0.5)
  rrect67% 0.4x0.3 smd paste-0.05 mask-0.05: 2(-0.3,0) 3(-0.3,-0.5) 4(0.3,-0.5) 5(0.3,0) 6(0.3,0.5)
  body extent -0.5,-0.72 0.5,0.73, height 0.58
FCC_disclaimer [mil]
Fiducial10-20 [mm]
  round 1 smd mask+0.5: 1(0,0)
  Top Layer keep-out circle w1.178: c0,0 r0.5
FP-BUK9D23-40EX_SOT1220-MFG [mm]
  rrect29% 0.43x0.35 smd paste-1000 mask+0: 1(-0.935,0.65) 2(-0.935,0) 3(-0.935,-0.65) 4(0.935,-0.65) 5(0.935,0) 6(0.935,0.65)
  rrect9% 1.1x1.25 smd paste-1000 mask+0: 7(0,0.285)
  rrect29% 0.66x0.35 smd paste-1000 mask+0: 8(0,-0.775)
  silkscreen extent -1.77,-1.35 1.05,1.35, body extent -1.25,-1.15 1.25,1.15, height 0.25
FP-MTLW-102-07-G-S-230_HDR2-MFG [mm]
  rrect7% 1.52x1.52 hole 1.02 paste-1000 mask+0: 1(-1.27,0)
  round 1.52 hole 1.02 paste-1000 mask+0: 2(1.27,0)
  silkscreen extent -3.27,-1.31 2.67,1.31, body extent -2.77,-1.41 2.77,1.41, height 0.25
Harwin_D3082-05 [mm] "Shorting Plug, 10.16mm spacing, TH"
  round 1.8 hole 1.3: 1(-5.08,0) 2(5.08,0)
  silkscreen extent -3.9,-0.53 3.9,0.53, body extent -5.6,-0.52 5.61,0.52, height 6.63
IEC_HotSurface_Small [mil]
  silkscreen extent -107,-93 107,92
Keystone5000 [mil] "For Keystone 500x miniature loop terminals"
  round 80 hole 40: 1(0,0)
  silkscreen extent -52,-52 52,52, body extent -49,-49 49,49, height 182
Keystone5001 [mil] "For Keystone 500x miniature loop terminals"
  round 80 hole 40: 1(0,0)
  silkscreen extent -52,-52 52,52, body extent -49,-49 49,49, height 182
Keystone5002 [mil] "For Keystone 500x miniature loop terminals"
  round 80 hole 40: 1(0,0)
  silkscreen extent -52,-52 52,52, body extent -49,-49 49,49, height 182
Keystone5005 [mil] "Keystone Compact loops"
  round 87 hole 63: 1(0,0)
  silkscreen extent -70,-70 70,70, body extent -63,-63 62,63, height 225
Keystone_1902C [mil] "Hex Standoff, 4-40 threaded, nylon"
  round 1 on Mech4: 0(0,0)
  body extent -145,-126 146,126, height 501
Label_650x200 [mil] "Thermal Transfer Label"
  round 1 on Mech13: 0(0,0)
  silkscreen extent -325,-100 325,100, body extent -325,-100 325,100, height 1
LED_LTST-C170_Red [mm] "LITE-ON"
  rect 1.2x1.2 smd: 1(-1.05,0) 2(1.05,0)
  silkscreen extent -1.6,-1 2.2,1, body extent -1.05,-0.67 1.05,0.67, height 1.1
LED_LTST-C190 [mm] "Lite-On"
  rect 0.8x0.8 smd: 1(-0.75,0) 2(0.75,0)
  silkscreen extent -1.1,-0.8 1.8,0.8, body extent -0.85,-0.45 0.85,0.45, height 0.9
LED_LTST-C190_Red [mm] "Lite-On"
  rect 0.8x0.8 smd: 1(-0.75,0) 2(0.75,0)
  silkscreen extent -1.1,-0.8 1.8,0.8, body extent -0.85,-0.45 0.85,0.45, height 0.9
LTST-C170KGKT_Green [mm] "LITE-ON"
  rect 1.2x1.2 smd: 1(-1.05,0) 2(1.05,0)
  silkscreen extent -1.6,-1 2.2,1, body extent -1.05,-0.67 1.05,0.67, height 1.1
Molex_1051640001 [mm] "Receptacle, USB 2.0, Micro B, 5 Pos, 0.65mm Pitch, R/A, SMT"
  rrect22% 0.45x1.38 smd: 1(1.3,4.11) 2(0.65,4.11) 3(0,4.11) 4(-0.65,4.11) 5(-1.3,4.11)
  rrect7% 1.475x2.1 smd: 6(-2.462,3.75) 11(2.462,3.75)
  rrect100% 1.4x2.1 hole 0.6 slot 1.3 at 90 deg: 7(-3.95,1.45) 10(3.95,1.45)
  rrect7% 1.375x1.9 smd: 8(-0.937,1.45) 9(0.937,1.45)
  silkscreen extent 1.2,5.1 1.4,5.4, body extent -4.1,-0.7 4.1,4.47, height 2.45
Murata_CSTCR_G [mm] "Murata"
  rect 0.4x2.6 smd: 1(-1.5,0) 2(0,0) 3(1.5,0)
  Top Layer region: 1.1,-1.301 1.1,-0.801 1.9,-0.801 1.9,-1.301
  Top Layer region: 1.1,0.8 1.9,0.8 1.9,1.3 1.1,1.3
  Top Layer region: -1.9,-1.301 -1.9,-0.801 -1.1,-0.801 -1.1,-1.301
  Top Layer region: -1.9,0.8 -1.1,0.8 -1.1,1.3 -1.9,1.3
  Top Layer region: -0.4,-1.301 -0.4,-0.801 0.4,-0.801 0.4,-1.301
  Top Layer region: -0.4,0.8 0.4,0.8 0.4,1.3 -0.4,1.3
  body extent -2.25,-1 2.25,1, height 1.16
Net-Tie_50milWide_30milLong [mil] "50mil net tie, no solder mask opening, no solder paste"
  rect 30x50 smd paste-20 mask-20: 1(-15,0) 2(15,0)
"NY PMS 440 0025 PH" [mm] "4-40 nylon screw and mounting hole"
  round 8 hole 3.2: 1(0,0)
  body extent -3.3,-3.3 3.3,3.3, height 2.69
On-Shore_ED120_3DS [mm] "ONSHORE"
  rrect5% 2x2 hole 1.25: 1(-5.08,0)
  round 2 hole 1.25: 2(0,0) 3(5.08,0)
  silkscreen extent -8.14,-4 7.5,5, body extent -8.32,-4 7.62,5, height 13
PBC03SAAN [mm] "Sullins 100mil, 1x3, 230 mil above insulator"
  rect 1.65x1.65 hole 1.016: 1(-2.54,0)
  round 1.65 hole 1.016: 2(0,0) 3(2.54,0)
  silkscreen extent -3.81,-1.27 3.81,1.27, body extent -3.81,-1.27 3.81,1.27, height 8.38
PT0048A-MFG [mm] "Thin QFP, 48-Leads, Body 7x7mm, Pitch 0.5mm, IPC Medium Density"
  rrect33% 1.4x0.3 smd paste-1000 mask+0: 1(-4.25,2.75) 2(-4.25,2.25) 3(-4.25,1.75) 4(-4.25,1.25) 5(-4.25,0.75) 6(-4.25,0.25) 7(-4.25,-0.25) 8(-4.25,-0.75) 9(-4.25,-1.25) 10(-4.25,-1.75) 11(-4.25,-2.25) 12(-4.25,-2.75) 25(4.25,-2.75) 26(4.25,-2.25) 27(4.25,-1.75) 28(4.25,-1.25) 29(4.25,-0.75) 30(4.25,-0.25) 31(4.25,0.25) 32(4.25,0.75) 33(4.25,1.25) 34(4.25,1.75) 35(4.25,2.25) 36(4.25,2.75)
  rrect33% 0.3x1.4 smd paste-1000 mask+0: 13(-2.75,-4.25) 14(-2.25,-4.25) 15(-1.75,-4.25) 16(-1.25,-4.25) 17(-0.75,-4.25) 18(-0.25,-4.25) 19(0.25,-4.25) 20(0.75,-4.25) 21(1.25,-4.25) 22(1.75,-4.25) 23(2.25,-4.25) 24(2.75,-4.25) 37(2.75,4.25) 38(2.25,4.25) 39(1.75,4.25) 40(1.25,4.25) 41(0.75,4.25) 42(0.25,4.25) 43(-0.25,4.25) 44(-0.75,4.25) 45(-1.25,4.25) 46(-1.75,4.25) 47(-2.25,4.25) 48(-2.75,4.25)
  silkscreen extent -5.65,-3.6 3.6,3.6, body extent -5.05,-5.05 5.05,5.05, height 0.25
REE0036A-MFG [mm]
  rrect50% 0.6x0.2 smd paste+0 mask+0: 1(-1.9,1.8) 2(-1.9,1.4) 3(-1.9,1) 4(-1.9,0.6) 5(-1.9,0.2) 6(-1.9,-0.2) 7(-1.9,-0.6) 8(-1.9,-1) 9(-1.9,-1.4) 10(-1.9,-1.8) 19(1.9,-1.8) 20(1.9,-1.4) 21(1.9,-1) 22(1.9,-0.6) 23(1.9,-0.2) 24(1.9,0.2) 25(1.9,0.6) 26(1.9,1) 27(1.9,1.4) 28(1.9,1.8)
  rrect50% 0.2x0.6 smd paste+0 mask+0: 11(-1.4,-2.4) 12(-1,-2.4) 13(-0.6,-2.4) 14(-0.2,-2.4) 15(0.2,-2.4) 16(0.6,-2.4) 17(1,-2.4) 18(1.4,-2.4) 29(1.4,2.4) 30(1,2.4) 31(0.6,2.4) 32(0.2,2.4) 33(-0.2,2.4) 34(-0.6,2.4) 35(-1,2.4) 36(-1.4,2.4)
  rrect7% 2.7x3.7 smd paste-1000 mask+0: 37(0,0)
  silkscreen extent -2.87,-2.55 2.05,2.55, body extent -2.3,-2.8 2.3,2.8, height 0.25
SNT-100-BK-G [mil] "Samtec STEP model"
  round 1 on Mech3: 0(0,0)
  body extent -100,-50 100,50, height 344
SOD-323 [mm] "NXP recommended land pattern"
  rect 0.6x0.6 smd paste-0.05: 1(-1.1,0) 2(1.1,0)
  silkscreen extent -2.06,-0.86 1.53,0.86, body extent -1.3,-0.67 1.3,0.68, height 1.1
SOD-523F [mm] "COMCHIP"
  rect 0.6x0.8 smd paste-0.05: 1(-0.85,0) 2(0.85,0)
  silkscreen extent -1.92,-0.87 1.1,0.87, body extent -0.9,-0.5 0.9,0.5, height 0.85
SOT-23L [mm] "SOT23, 3-Leads, Body 2.9x1.3mm, Pitch 0.95mm, Lead Span 2.5mm, IPC High Density"
  rrect50% 0.8x0.6 smd: 1(-1.1,0.95) 2(-1.1,-0.95) 3(1.1,0)
  silkscreen extent -1.5,-1.5 0.7,1.5, body extent -1.16,-1.45 1.21,1.45, height 1
SRP1038A [mm] "SMD, 2-Leads, Body 11x10mm"
  rect 4.1x3.5 smd: 1(-4.75,0) 2(4.75,0)
  silkscreen extent -5,-5 5,5, body extent -5.2,-5 5.2,5, height 3.75
SSOP28_N [mm] "SOP, 28-Leads, Body 10.2x5.3mm, Pitch 0.65mm, IPC Medium Density"
  oval 2.1x0.45 smd: 1(-3.45,4.225) 2(-3.45,3.575) 3(-3.45,2.925) 4(-3.45,2.275) 5(-3.45,1.625) 6(-3.45,0.975) 7(-3.45,0.325) 8(-3.45,-0.325) 9(-3.45,-0.975) 10(-3.45,-1.625) 11(-3.45,-2.275) 12(-3.45,-2.925) 13(-3.45,-3.575) 14(-3.45,-4.225) 15(3.45,-4.225) 16(3.45,-3.575) 17(3.45,-2.925) 18(3.45,-2.275) 19(3.45,-1.625) 20(3.45,-0.975) 21(3.45,-0.325) 22(3.45,0.325) 23(3.45,0.975) 24(3.45,1.625) 25(3.45,2.275) 26(3.45,2.925) 27(3.45,3.575) 28(3.45,4.225)
  silkscreen extent -3.57,-5.3 2,5.3, body extent -2.7,-5.3 2.7,5.3, height 2
SW_434121025816 [mm] "SMD, 2-Leads, Body 6x3.9mm, Pitch 6.5mm"
  rect 1.5x1.4 smd: 1(-3.25,0) 2(3.25,0)
  silkscreen extent -3,-1.95 3,1.95, body extent -3.65,-1.95 3.65,1.95, height 2.5
SW_B12AP [mm] "NKK Switches"
  rect 1.35x1.35 hole 0.85 paste+0: 1(-1,2.54)
  round 1.35 hole 0.85 paste+0: 2(-1,0) 3(-1,-2.54)
  silkscreen extent -4.27,-4.4 3.4,4.4, body extent -3.4,-4.39 3.4,4.39, height 22.87
TI_Stacked_Overlay_Small [mil]
  silkscreen extent -418,-98 418,98
TSW-103-07-G-D [mm] "Samtec 100mil, 2x3, 230 mil above insulator"
  rect 1.65x1.65 hole 1.016: 1(-2.54,-1.27)
  round 1.65 hole 1.016: 2(-2.54,1.27) 3(0,-1.27) 4(0,1.27) 5(2.54,-1.27) 6(2.54,1.27)
  silkscreen extent -4.84,-2.54 3.81,2.54, body extent -3.81,-2.54 3.81,2.54, height 8.38
TSW-104-07-G-S [mm] "Samtec 100mil, 1x4, 230 mil above insulator"
  rrect50% 1.65x1.65 hole 1.016: 1(-3.81,0)
  round 1.65 hole 1.016: 2(-1.27,0) 3(1.27,0) 4(3.81,0)
  body extent -5.08,-1.27 5.08,1.27, height 8.38
TSW-116-07-G-D [mm] "Samtec 100mil, 2x16, 230 mil above insulator"
  rrect6% 1.65x1.65 hole 1.016: 1(-19.05,-1.27)
  round 1.65 hole 1.016: 2(-19.05,1.27) 3(-16.51,-1.27) 4(-16.51,1.27) 5(-13.97,-1.27) 6(-13.97,1.27) 7(-11.43,-1.27) 8(-11.43,1.27) 9(-8.89,-1.27) 10(-8.89,1.27) 11(-6.35,-1.27) 12(-6.35,1.27) 13(-3.81,-1.27) 14(-3.81,1.27) 15(-1.27,-1.27) 16(-1.27,1.27) 17(1.27,-1.27) 18(1.27,1.27) 19(3.81,-1.27) 20(3.81,1.27) 21(6.35,-1.27) 22(6.35,1.27) 23(8.89,-1.27) 24(8.89,1.27) 25(11.43,-1.27) 26(11.43,1.27) 27(13.97,-1.27) 28(13.97,1.27) 29(16.51,-1.27) 30(16.51,1.27) 31(19.05,-1.27) 32(19.05,1.27)
  silkscreen extent -21.34,-2.54 20.32,2.54, body extent -20.32,-2.54 20.32,2.54, height 8.38
WEEE_Minimum [mil] "WEEElie bin"

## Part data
C1: library part CMP-0080104-1, "CAP, CERM, 1 µF, 16 V,+/- 10%, X7R, AEC-Q200 Grade 1, 0603", Cap_Case=0603, Manufacturer="Taiyo Yuden", Supplier Part Number 1=587-3305-1-ND, TempCo=X7R, Tolerance_%=10%, Value2=16V, ValueDisplayed=1µF
C2: library part CMP-0006812-1, "CAP, CERM, 100 pF, 10 V, +/- 10%, X7R, 0603", Cap_Case=0603, Manufacturer=AVX, Supplier Part Number 1=0603ZC101KAT2A-ND, TempCo=X7R, Tolerance_%=10%, Value1=Unknown, Value2=10V, ValueDisplayed=100pF
C3 C5: library part CMP-0086190-1, "CAP, CERM, 1 µF, 6.3 V,+/- 10%, X7R, AEC-Q200 Grade 1, 0603", Cap_Case=0603, Manufacturer=Kemet, TempCo=X7R, Tolerance_%=10%, Value2=6.3V, ValueDisplayed=1µF
C4 C7: library part CMP-0006289-1, "CAP, CERM, 0.1 uF, 50 V, +/- 10%, X6S, 0402", Cap_Case=0402, Manufacturer=TDK, Supplier Part Number 1=445-7356-1-ND, TempCo=X6S, Tolerance_%=10%, Value1="0.039064 ohm", Value2=50V, ValueDisplayed=0.1uF
C6: library part CMP-0009229-1, "CAP, CERM, 10 uF, 63 V, +/- 10%, X7R, 1210", Cap_Case=1210, Manufacturer=MuRata, Supplier Part Number 1=490-9970-1-ND, TempCo=X7R, Tolerance_%=10%, Value1=Unknown, Value2=63V, ValueDisplayed=10uF
C10 C11 C13: library part CMP-0006815-4, "CAP, CERM, 0.1 uF, 10 V, +/- 10%, X7R, 0603", Cap_Case=0603, Manufacturer=AVX, Supplier Part Number 1=478-7939-1-ND, TempCo=X7R, Tolerance_%=10%, Value1=Unknown, Value2=10V, ValueDisplayed=0.1uF
C12: library part CMP-0007498-4, "CAP, CERM, 4.7 uF, 10 V, +/- 20%, X7R, 0603", Cap_Case=0603, Manufacturer=MuRata, TempCo=X7R, Tolerance_%=20%, Value1=Unknown, Value2=10V, ValueDisplayed=4.7uF
C14: library part CMP-0006826-4, "CAP, CERM, 1000 pF, 16 V, +/- 10%, X7R, 0603", Cap_Case=0603, Manufacturer="Wurth Elektronik", Supplier Part Number 1=710-885012206034, TempCo=X7R, Tolerance_%=10%, Value1=Unknown, Value2=16V, ValueDisplayed=1000pF
C15: library part CMP-0007696-2, "CAP, CERM, 1 uF, 50 V, +/- 10%, X7R, 0805", Cap_Case=0805, Manufacturer="Wurth Elektronik", Supplier Part Number 1=710-885012207103, TempCo=X7R, Tolerance_%=10%, Value1=Unknown, Value2=50V, ValueDisplayed=1uF
C16: library part CMP-0009912-2, "CAP, AL, 330 uF, 63 V, +/- 20%, AEC-Q200 Grade 2, TH", Cap_Case=12.5x20mm, Manufacturer=Chemi-Con, Supplier Part Number 1=565-2043-ND, Tolerance_%=20%, Value1=Unknown, Value2=63V, ValueDisplayed=330uF
C17 C24: library part CMP-0008801-2, "CAP, CERM, 1 uF, 100 V, +/- 10%, X7R, 1206", Cap_Case=1206, Manufacturer=Samsung, Supplier Part Number 1=1276-1838-1-ND, TempCo=X7R, Tolerance_%=10%, Value1=Unknown, Value2=100V, ValueDisplayed=1uF
C18 C23: library part CMP-0007099-4, "CAP, CERM, 0.1 uF, 100 V, +/- 10%, X7S, AEC-Q200 Grade 1, 0603", Cap_Case=0603, Manufacturer=TDK, Supplier Part Number 1=445-6938-1-ND, TempCo=X7S, Tolerance_%=10%, Value1="0.04959 ohm", Value2=100V, ValueDisplayed=0.1uF
C19 C22: library part CMP-0007082-4, "CAP, CERM, 0.01 uF, 100 V, +/- 10%, X7R, AEC-Q200 Grade 1, 0603", Cap_Case=0603, Manufacturer=TDK, Supplier Part Number 1=445-5812-1-ND, TempCo=X7R, Tolerance_%=10%, Value1="0.235428 ohm", Value2=100V, ValueDisplayed=0.01uF
C20 C21: library part CMP-0007081-4, "CAP, CERM, 1000 pF, 100 V, +/- 10%, X7R, AEC-Q200 Grade 1, 0603", Cap_Case=0603, Manufacturer=TDK, Supplier Part Number 1=445-5806-1-ND, TempCo=X7R, Tolerance_%=10%, Value1="1.97137 ohm", Value2=100V, ValueDisplayed=1000pF
D1: library part CMP-0002888-2, "LED, Green, SMD", Color=Green, Manufacturer=Lite-On, PartNumber=LTST-C170KGKT, Value1=W, Value2=2V
D2 D3: library part CMP-0002829-3, "LED, Red, SMD", Color=red, Manufacturer=Lite-On, PartNumber=LTST-C170KRKT, Value1=W, Value2=2V
D4: library part CMP-0002888-2, "LED, Green, SMD", Color=Green, Manufacturer=Lite-On, Value1=W, Value2=2V
D5: library part CMP-0028882-2, "Diode, Schottky, 40 V, 0.75 A, AEC-Q101, SOD-323", Manufacturer="Infineon Technologies", Value1=0.75A, Value2=0.74V
D6: library part CMP-0078131-2, "LED, Red, SMD", Color=Red, Manufacturer=Lite-On, Power_TotalModule=62.5mW, Value1=.0625W, Value2=2V
D7: library part CMP-0002827-2, "LED, Green, SMD", Color=green, Manufacturer=Lite-On, Power_TotalModule=100mW, Supplier Part Number 1=160-1183-1-ND, Value1=0.1W, Value2=2.1V
D8: library part CMP-0076943-3, "Diode, Switching, 90 V, 0.1 A, SOD-523F", Manufacturer="Comchip Technology", Value1=0.1A, Value2=1V
FID1 FID2 FID3: library part CMP-0077181-1, "Fiducial mark.  There is nothing to buy or mount.", Manufacturer=N/A
H1 H2 H3 H4: library part CMP-0003617-1, "Machine Screw, Round, #4-40 x 1/4, Nylon, Philips panhead", Manufacturer="B&F Fastener Supply", Supplier Part Number 1=H542-ND
H5 H6 H7 H8: library part CMP-0003610-1, "Standoff, Hex, 0.5\"L #4-40 Nylon", Manufacturer=Keystone, PartNumber=1902C, Supplier Part Number 1=36-1902C-ND
J1: library part CMP-0075406-2, "Header, 100mil, 3x2, Gold, TH", Color=Black, Current_A=6.3A, Manufacturer=Samtec, PartNumber=TSW-103-07-G-D, Supplier Part Number 1=SAM1028-03-ND, Voltage_V=550V
J2: library part CMP-0055311-1, "Receptacle, USB 2.0, Micro B, 5 Position, R/A, SMT", Color=Black, Current_A=1.8A, Manufacturer=Molex, Supplier Part Number 1=WM11263CT-ND, Voltage_V=30V
J3 J5: library part CMP-0002334-1, "Header, 100mil, 3x1, Gold, TH", Manufacturer="Sullins Connector Solutions", PartNumber=PBC03SAAN, Supplier Part Number 1=S1011E-03-ND
J4: library part CMP-0075409-2, "Header, 100mil, 4x1, Gold, TH", Color=Black, Current_A=6.3A, Manufacturer=Samtec, Supplier Part Number 1=SAM1029-04-ND, Voltage_V=550V
J6: library part CMP-0075429-1, "Header, 100mil, 16x2, Gold, TH", Color=Black, Current_A=6.3A, Manufacturer=Samtec, Supplier Part Number 1=SAM1028-16-ND, Voltage_V=550V
J7 J8: library part CMP-0074911-1, "Terminal Block, 5.08 mm, 3x1, Brass, TH", Color=Blue, Current_A=15A, Manufacturer="On-Shore Technology", PartNumber=ED120/3DS, Supplier Part Number 1=ED1610-ND, Voltage_V=300V
JP1: library part CMP-0090697-1, "Conn Unshrouded Header HDR 2 POS 2.54mm Solder ST Thru-Hole", Current_A=5.2A, Digikey Part Number=SAM15239-ND, Manufacturer=Samtec, Mouser Part Number=200-MTLW10207GS230, Operating Temperature Range="-55°C to +125°C", Part Number=MTLW-102-07-G-S-230
L3: library part CMP-0084877-1, "Inductor, Ferrite Bead, Ferrite, 3 A, 120 ohm, AEC-Q200 Grade 1, SMD", Manufacturer=MuRata, Value1="120 ohm", Value2=3A
L4: library part CMP-0056795-1, "Inductor, Shielded, Powdered Iron, 1 uH, 18 A, 0.003 ohm, AEC-Q200 Grade 1, SMD", Manufacturer=Bourns, Supplier Part Number 1=SRP1038A-1R0MCT-ND, Value1="0.003 ohm", Value2=18A, ValueDisplayed=1uH
LBL1: library part CMP-0003625-1, Manufacturer=Brady, Supplier Part Number 1=97C5133
Logo1: library part CMP-0074844-1
Logo2: library part CMP-0074838-1, "Texas Instrument Corporate Signature"
Logo3: library part CMP-0074847-1, "FCC_disclaimer"
Logo4: library part CMP-0074769-1
LOGO5 LOGO6: library part CMP-0074837-1, "IEC 61010-1 Hot Surface Warning"
NT2: library part CMP-0078142-4, "Single point connection between nets.", Manufacturer=N/A
Q1: library part CMP-0000467-2, "Transistor, NPN, 80 V, 1.5 A, AEC-Q101, SOT-23", Manufacturer="Diodes Inc.", Supplier Part Number 1=FMMT620CT-ND, Value1="1.5 A", Value2=900
Q2: library part CMP-0088880-1, "N-Channel 40V 8A (Ta) 15W (Tc) Surface Mount DFN2020MD-6", Digikey Part Number=1727-7413-1-ND, Drain To Source Breakdown Voltage=40V, Input Capacitace At Vds="637pF @ 20V", Manufacturer=Nexperia, Mouser Part Number=771-BUK9D23-40EX, Operating Temperature Range="-55°C to +175°C", Power_W=2.3W, Pulse Drain Current=76A, Typ Forward Diode Voltage=0.8V
R1 R2 R6 R7: library part CMP-0023626-2, "RES, 10.0 k, 0.01%, 0.063 W, 0603", Manufacturer="Stackpole Electronics Inc", Power_W=63mW, Supplier Part Number 1=RNCF0603TKY10K0CT-ND, TempCo="5 ppm/C", Tolerance_%=0.01%, Value2=0.063W, Value_Code=10k0, ValueDisplayed=10.0k
R4: library part CMP-0001776-2, "Trimmer Potentiometer, 25kohm, 0.5W, TH", Manufacturer=Bourns, Supplier Part Number 1=3352T-253LF-ND
R5 R15 R16 R21 R22 R23 R24 R27 R28 R29 R30: library part CMP-0025874-4, "RES, 0, 5%, 0.1 W, AEC-Q200 Grade 0, 0603", Manufacturer=Panasonic, Power_W=100mW, Supplier Part Number 1=P0.0GCT-ND, TempCo="600 ppm/C", Tolerance_%=5%, Value2=0.1W, Value_Code=0000, ValueDisplayed=0
R9: library part CMP-0024269-1, "RES, 47.0, 0.1%, 0.1 W, 0603", Manufacturer="Yageo America", Power_W=100mW, TempCo="25 ppm/C", Tolerance_%=0.1%, Value2=0.1W, Value_Code=47R0, ValueDisplayed=47.0
R10: library part CMP-0023337-3, "RES, 10.0 k, 1%, 0.1 W, 0603", Manufacturer="Vishay Draloric", Power_W=100mW, Supplier Part Number 1=541-1784-1-ND, TempCo="100 ppm/C", Tolerance_%=1%, Value2=0.1W, Value_Code=10k0, ValueDisplayed=10.0k
R13 R14: library part CMP-0024840-3, "RES, 1.74 k, 0.5%, 0.1 W, 0603", Manufacturer="Yageo America", Power_W=100mW, TempCo="50 ppm/C", Tolerance_%=0.5%, Value2=0.1W, Value_Code=1k74, ValueDisplayed=1.74k
R17 R18: library part CMP-0022895-5, "RES, 1.00 k, 1%, 0.1 W, 0603", Manufacturer=Yageo, Power_W=100mW, Supplier Part Number 1=311-1.00KHRCT-ND, TempCo="100 ppm/C", Tolerance_%=1%, Value2=0.1W, Value_Code=1k00, ValueDisplayed=1.00k
R19: library part CMP-0025879-1, "RES, 2.2 k, 5%, 0.1 W, AEC-Q200 Grade 0, 0603", Manufacturer=Panasonic, Power_W=100mW, Supplier Part Number 1=P2.2KGCT-ND, TempCo="200 ppm/C", Tolerance_%=5%, Value2=0.1W, Value_Code=2k20, ValueDisplayed=2.2k
R20: library part CMP-0024300-2, "RES, 4.70 k, 0.1%, 0.1 W, 0603", Manufacturer="Yageo America", Power_W=100mW, TempCo="25 ppm/C", Tolerance_%=0.1%, Value2=0.1W, Value_Code=4k70, ValueDisplayed=4.70k
R31: library part CMP-0025925-5, "RES, 47 k, 5%, 0.1 W, 0603", Manufacturer=Yageo, Power_W=100mW, Supplier Part Number 1=311-47KGRCT-ND, TempCo="100 ppm/C", Tolerance_%=5%, Value2=0.1W, Value_Code=47k0, ValueDisplayed=47k
R32 R33: library part CMP-0025924-5, "RES, 470, 5%, 0.1 W, 0603", Manufacturer=Yageo, Power_W=100mW, Supplier Part Number 1=311-470GRCT-ND, TempCo="100 ppm/C", Tolerance_%=5%, Value2=0.1W, Value_Code=470R, ValueDisplayed=470
R34 R35: library part CMP-0025701-4, "RES, 10 k, 5%, 0.1 W, AEC-Q200 Grade 0, 0603", Manufacturer=Vishay-Dale, Power_W=100mW, Supplier Part Number 1=541-10KGCT-ND, TempCo="200 ppm/C", Tolerance_%=5%, Value2=0.1W, Value_Code=10k0, ValueDisplayed=10k
R36: library part CMP-0018760-2, "RES, 0, 5%, 0.25 W, AEC-Q200 Grade 0, 1206", Manufacturer=Vishay-Dale, Power_W=250mW, Supplier Part Number 1=541-2239-1-ND, TempCo=ppm/C, Tolerance_%=5%, Value2=0.25W, Value_Code=0000, ValueDisplayed=0
S1 S2: library part CMP-0002155-2, "SWITCH TOGGLE SPDT 0.4VA 28V", CurrentRating_mA=100A, Manufacturer="NKK Switches", PartNumber=B12AP, Supplier Part Number 1=360-1012-ND
S4: library part CMP-0002196-2, "Switch, Tactile, SPST, 12 V, SMD", CurrentRating_mA=50A, Manufacturer="Wurth Elektronik", PartNumber=434121025816, Supplier Part Number 1=31T8978
SH-J1 SH-J2 SH-J3 SH-J4 SH-J5 SH-J6 SH-J7 SH-J8 SH-J9 SH-J10 SH-J11 SH-J12 SH-J13 SH-J14 SH-J15 SH-J16 SH-J17 SH-J18 SH-J19 SH-J21: library part CMP-0003623-3, "Shunt, 100mil, Gold plated, Black", Alternate Manufacturer=3M, Alternate PartNumber=969102-0000-DA, Manufacturer=Samtec, Supplier Part Number 1=SAM8858-ND
TP1 TP2 TP3 TP7 TP8 TP14 TP15 TP16 TP17 TP35: library part CMP-0055139-1, "Test Point, Miniature, White, TH", Color=White, Manufacturer=Keystone, PartNumber=5002, Supplier Part Number 1=36-5002-ND
TP5 TP6 TP9 TP11 TP12 TP13 TP18 TP19 TP20 TP21 TP22: library part CMP-0055137-1, "Test Point, Miniature, Red, TH", Color=Red, Manufacturer=Keystone, PartNumber=5000, Supplier Part Number 1=36-5000-ND
TP10 TP23 TP24: library part CMP-0055142-1, "Test Point, Compact, Red, TH", Color=Red, Manufacturer=Keystone, PartNumber=5005, Supplier Part Number 1=36-5005-ND
TP25 TP30 TP31 TP32 TP33 TP34: library part CMP-0055138-1, "Test Point, Miniature, Black, TH", Color=Black, Manufacturer=Keystone, PartNumber=5001, Supplier Part Number 1=36-5001-ND
TP26 TP27 TP28 TP29: library part CMP-0075110-1, "1mm Uninsulated Shorting Plug, 10.16mm spacing, TH", Manufacturer=Harwin, PartNumber=D3082-05, Supplier Part Number 1=952-1873-ND
U1: library part CMP-0096865-1, "High Speed Sensorless Trapezoidal Control Integrated FET BLDC Driver", Manufacturer="Texas Instruments", Max Supply Voltage=20V, Min Supply Voltage=4.5V, Nominal Supply Current=25mA, Operating Temperature Range="-40°C to +150°C", Switching Frequency=100kHz
U2: library part CMP-0004774-1, "USB to Serial UART, SSOP28", Manufacturer=FTDI, Supplier Part Number 1=768-1007-1-ND
U3: library part CMP-0043115-3, "4-Channel ESD Protection Array for High-Speed Data Interfaces, DRY0006A (USON-6)", Breakdown Voltage(Min)(V)=6, IO Capacitance(Typ)(pF)=1.6, IO Leakage Current(nA)=1, Manufacturer="Texas Instruments", Operating Temperature Range="-40 to 85 C", Rating=Catalog
U4: library part CMP-0089204-1, "CPU16 MSP430™ FRAM Microcontroller IC 16-Bit 24MHz 32KB (32K x 8) FRAM 48-LQFP (7x7)", Digikey Part Number=296-50261-1-ND, Frequency_Fixed=24MHz, Manufacturer="Texas Instruments", Max Supply Voltage=3.6V, Min Supply Voltage=1.8V, Mouser Part Number=595-MSP430FR2355TPTR, Operating Temperature Range="-40°C to +105°C"
Y2: library part CMP-0084387-1, "Resonator, 4 MHz, 39 pF, AEC-Q200 Grade 1, SMD", Frequency_Fixed=4MHz, Load Capacitance="39 pF", Manufacturer=MuRata
ZZ1: library part CMP-0003616-3
ZZ2: library part CMP-0077236-1
ZZ3: library part CMP-0077237-1
ZZ4: library part CMP-0077238-1

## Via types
v1: diameter 20, hole 10, Top Layer to Bottom Layer, tented both sides, 600 vias
v2: diameter 25, hole 10, Top Layer to Bottom Layer, tented both sides, 30 vias
v3: diameter 19.68, hole 7.87, Top Layer to Bottom Layer, tented both sides, 8 vias
v4: diameter 25, hole 10, Top Layer to Bottom Layer, 1 vias

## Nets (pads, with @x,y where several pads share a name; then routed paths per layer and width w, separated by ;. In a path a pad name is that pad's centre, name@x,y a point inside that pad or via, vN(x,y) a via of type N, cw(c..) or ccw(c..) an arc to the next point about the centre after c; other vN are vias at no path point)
3V3_MCU: C15.1 D5.1 J4.2 J5.2 R31.2 R32.2 R33.2 TP22.1 U4.6 | length 434.2
  Top Layer w10: R31.2@260.06,1637.5 v1(297.5,1637.5) ; 627.54,1275.51 640.11,1262.93 693.3,1262.93 v1(752.5,1262.93) ; v1(1131.95,1214.99) 1148.39,1231.43 R33.2@1182.08,1231.43 ; v1(1137.5,1370) 1181.88,1370 R32.2@1182.08,1370.2
  Top Layer w20: C15.1@572.03,1287.5 615.54,1287.5 627.54,1275.51 ; TP22.1@1175,525 1185.81,514.19 D5.1@1185.81,425
3V3COM: C11.1 D5.2 J5.3 TP18.1 U2.4 U2.17 | length 1382.9
  Top Layer w15: U2.17@581.82,569.59 581.82,635.04 644.88,698.09 746.19,698.09 786.55,738.45 U2.4@786.55,841.24 786.55,894.06 C11.1@819.58,927.09
  Top Layer w20: 786.55,738.45 TP18.1@1000,525 J5.3@1400,125
3V3EXT: J5.1 TP21.1 | length 485.1
  Top Layer w20: TP21.1@1175,125 1247.5,52.5 1527.5,52.5 J5.1@1600,125
5V_EXT: J3.1 TP20.1 | length 212.5
  Top Layer w20: J3.1@787.5,125 TP20.1@1000,125
5V_USB: C10.1 J3.3 L3.1 TP19.1 U3.6 | length 510.5
  Top Layer w10: v1(407.5,542.5) 414.91,549.91 U3.6@428.19,549.91
  Top Layer w30: 355.49,515.64 587.5,283.63 J3.3@587.5,125
  other v1: 349.64,538.74 349.78,565.08 349.64,594.33
5VCC: C12.2 C13.1 J3.2 U2.20 | length 440.1
  Top Layer w10: 658.6,461.54 U2.20@658.6,569.59
  Top Layer w25: J3.2@687.5,125 687.73,125.23 C13.1@687.73,456.96
AGND: C2.2 C3.1 C5.1 C10.2 C11.2 C12.1 C13.2 C14.2 C15.2 J2.5 J2.6 J2.7 J2.8 J2.9 J2.10 J2.11 J4.1 J6.1 J6.2 NT2.1 R4.3 R6.1 R7.1 R17.1 R19.1 R21.2 R22.2 R23.2 R24.2 R27.2 R28.2 R29.2 R30.2 R36.1 S4.2 TP26.1 TP26.2 TP27.1 TP27.2 TP30.1 TP31.1 TP32.1 TP33.1 U1.2 U1.22 U1.37 U2.7 U2.18 U2.21 U2.25 U2.26 U3.3 U4.7 Y2.2
  other v1: 108,66 308,66 408,66 508,66 608,66 708,66 808,66 908,66 1008,66 1108,66 1608,66 1708,66 458,166 858,166 958,166 1058,166 1258,166 1658,166 1758,166 408,266 508,266 808,266 908,266 1008,266 1108,266 1208,266 1308,266 1608,266 1708,266 358,366 458,366 858,366 958,366 1058,366 1458,366 1558,366 1658,366 1758,366 908,466 1008,466 1108,466 1408,466 1508,466 1608,466 1058,566 1458,566 1558,566 487.5,602.5 908,666 1008,666 1108,666 1308,666 1408,666 1508,666 1608,666 458,766 558,766 858,766 958,766 1058,766 1258,766 1358,766 1458,766 1558,766 1008,866 1108,866 1308,866 1408,866 1508,866 1608,866 2008,866 2108,866 2208,866 2508,866 2608,866 2708,866 925,962.5 258,966 358,966 458,966 558,966 658,966 758,966 1058,966 2258,966 2458,966 2558,966 2658,966 2758,966 2858,966 308,1066 408,1066 708,1066 1008,1066 1108,1066 1308,1066 1408,1066 1508,1066 1608,1066 2408,1066 2608,1066 2908,1066 858,1166 1358,1166 1458,1166 1558,1166 1958,1166 2058,1166 2158,1166 2258,1166 2458,1166 2208,1266 2408,1266 2608,1266 158,1366 1358,1366 1458,1366 1558,1366 1658,1366 2258,1366 208,1466 408,1466 508,1466 608,1466 708,1466 358,1566 458,1566 658,1566 858,1566 958,1566 2558,1566 2658,1566 408,1666 608,1666 708,1666 808,1666 908,1666 1008,1666 1108,1666 1908,1666 2008,1666 2208,1666 2508,1666 858,1766 958,1766 1058,1766 1158,1766 2258,1766 108,1866 208,1866 408,1866 508,1866 608,1866 808,1866 908,1866 1008,1866 1108,1866 1208,1866 1308,1866 2408,1866 258,1966 358,1966 1958,1966 2558,1966 408,2066 358,2166 458,2166 558,2166 658,2166 758,2166 1358,2166 1458,2166 308,2266 408,2266 508,2266 608,2266 708,2266 808,2266 1008,2266 1308,2266 1408,2266 1508,2266 1608,2266 1908,2266 2208,2266 2908,2266 158,2366 258,2366 358,2366 458,2366 1058,2366 1458,2366 1558,2366 1658,2366 1758,2366 1858,2366 2158,2366 2258,2366 108,2466 308,2466 508,2466 708,2466 808,2466 2108,2466 2208,2466 2308,2466 2408,2466 2508,2466 2608,2466 2708,2466 2808,2466 2908,2466 3008,2466 3108,2466 458,2566 558,2566 958,2566 1058,2566 1158,2566 1558,2566 1658,2566 1758,2566 1858,2566 1958,2566 2058,2566 2158,2566 2258,2566 2358,2566 2458,2566 2558,2566 2658,2566 2758,2566 2858,2566 2958,2566 408,2666 508,2666 608,2666 708,2666 808,2666 908,2666 1008,2666 1108,2666 1208,2666 1308,2666 1408,2666 1508,2666 1608,2666 1708,2666 1808,2666 1908,2666 2008,2666 2108,2666 2208,2666 2608,2666 2708,2666 3008,2666 358,2766 458,2766 558,2766 658,2766 758,2766 858,2766 958,2766 1058,2766 1158,2766 1258,2766 1358,2766 1458,2766 1558,2766 1658,2766 1758,2766 1858,2766 1958,2766 2058,2766 2158,2766 2658,2766 3058,2766
  other v3: 2862.03,1806.89 2911.24,1806.89 2823.64,1850.2 2862.03,1850.2 2911.24,1850.2 2949.63,1850.2 2862.03,1893.5 2911.24,1893.5
ALARM: D3.1 J6.9 R30.1 U1.35 | length 2427.2
  Top Layer w7.87: J6.9@1850,1150 2090.04,1390.04 2313.7,1390.04 D3.1@2386.16,1462.5 ; v2(2150,1525) 2212.5,1462.5 D3.1@2386.16,1462.5 ; v2(2167.5,1952.5) 2167.5,1961.59 2253.41,2047.5 2371.96,2047.5 R30.1@2552.9,2228.44 ; U1.35@2792.15,1810.83 2718.33,1810.83 2386.16,1478.66 D3.1@2386.16,1462.5
  Bottom Layer w7.87: v2(2150,1525) 2150,1935 v2(2167.5,1952.5)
